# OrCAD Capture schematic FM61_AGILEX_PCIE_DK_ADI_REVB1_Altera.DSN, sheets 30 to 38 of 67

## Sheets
30 Micro SD: size B
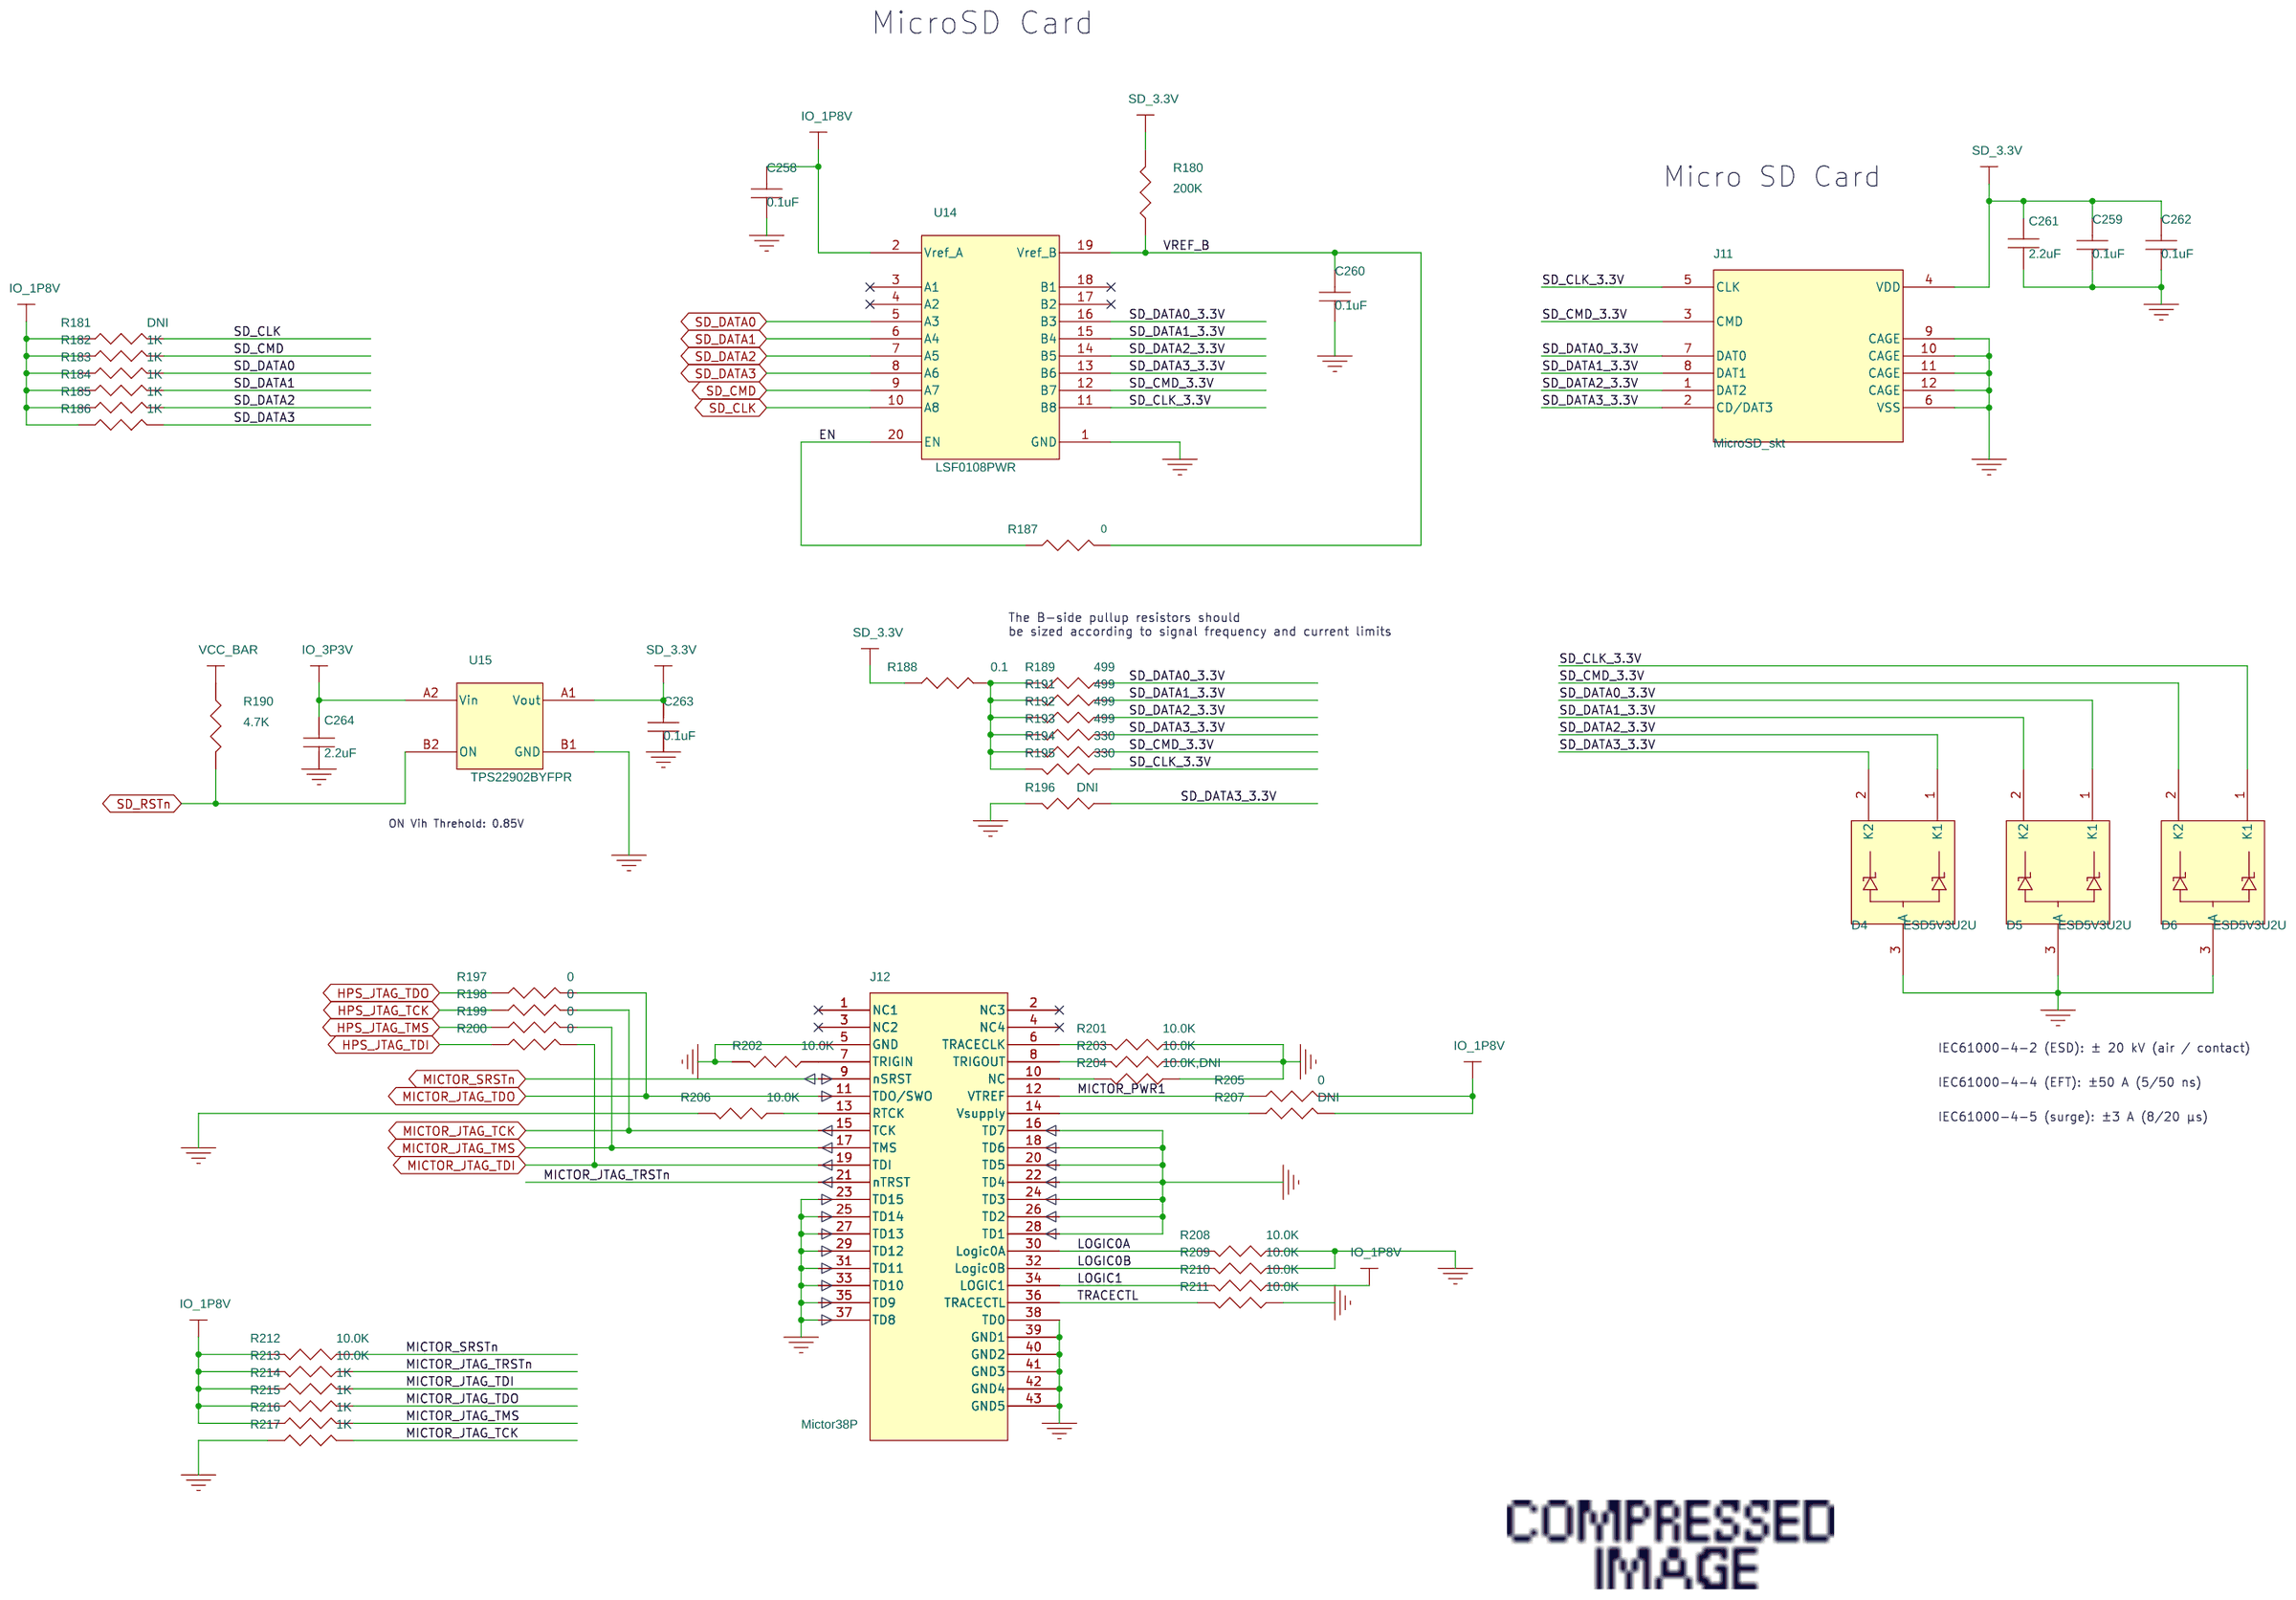
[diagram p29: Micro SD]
31 eMMC: size B
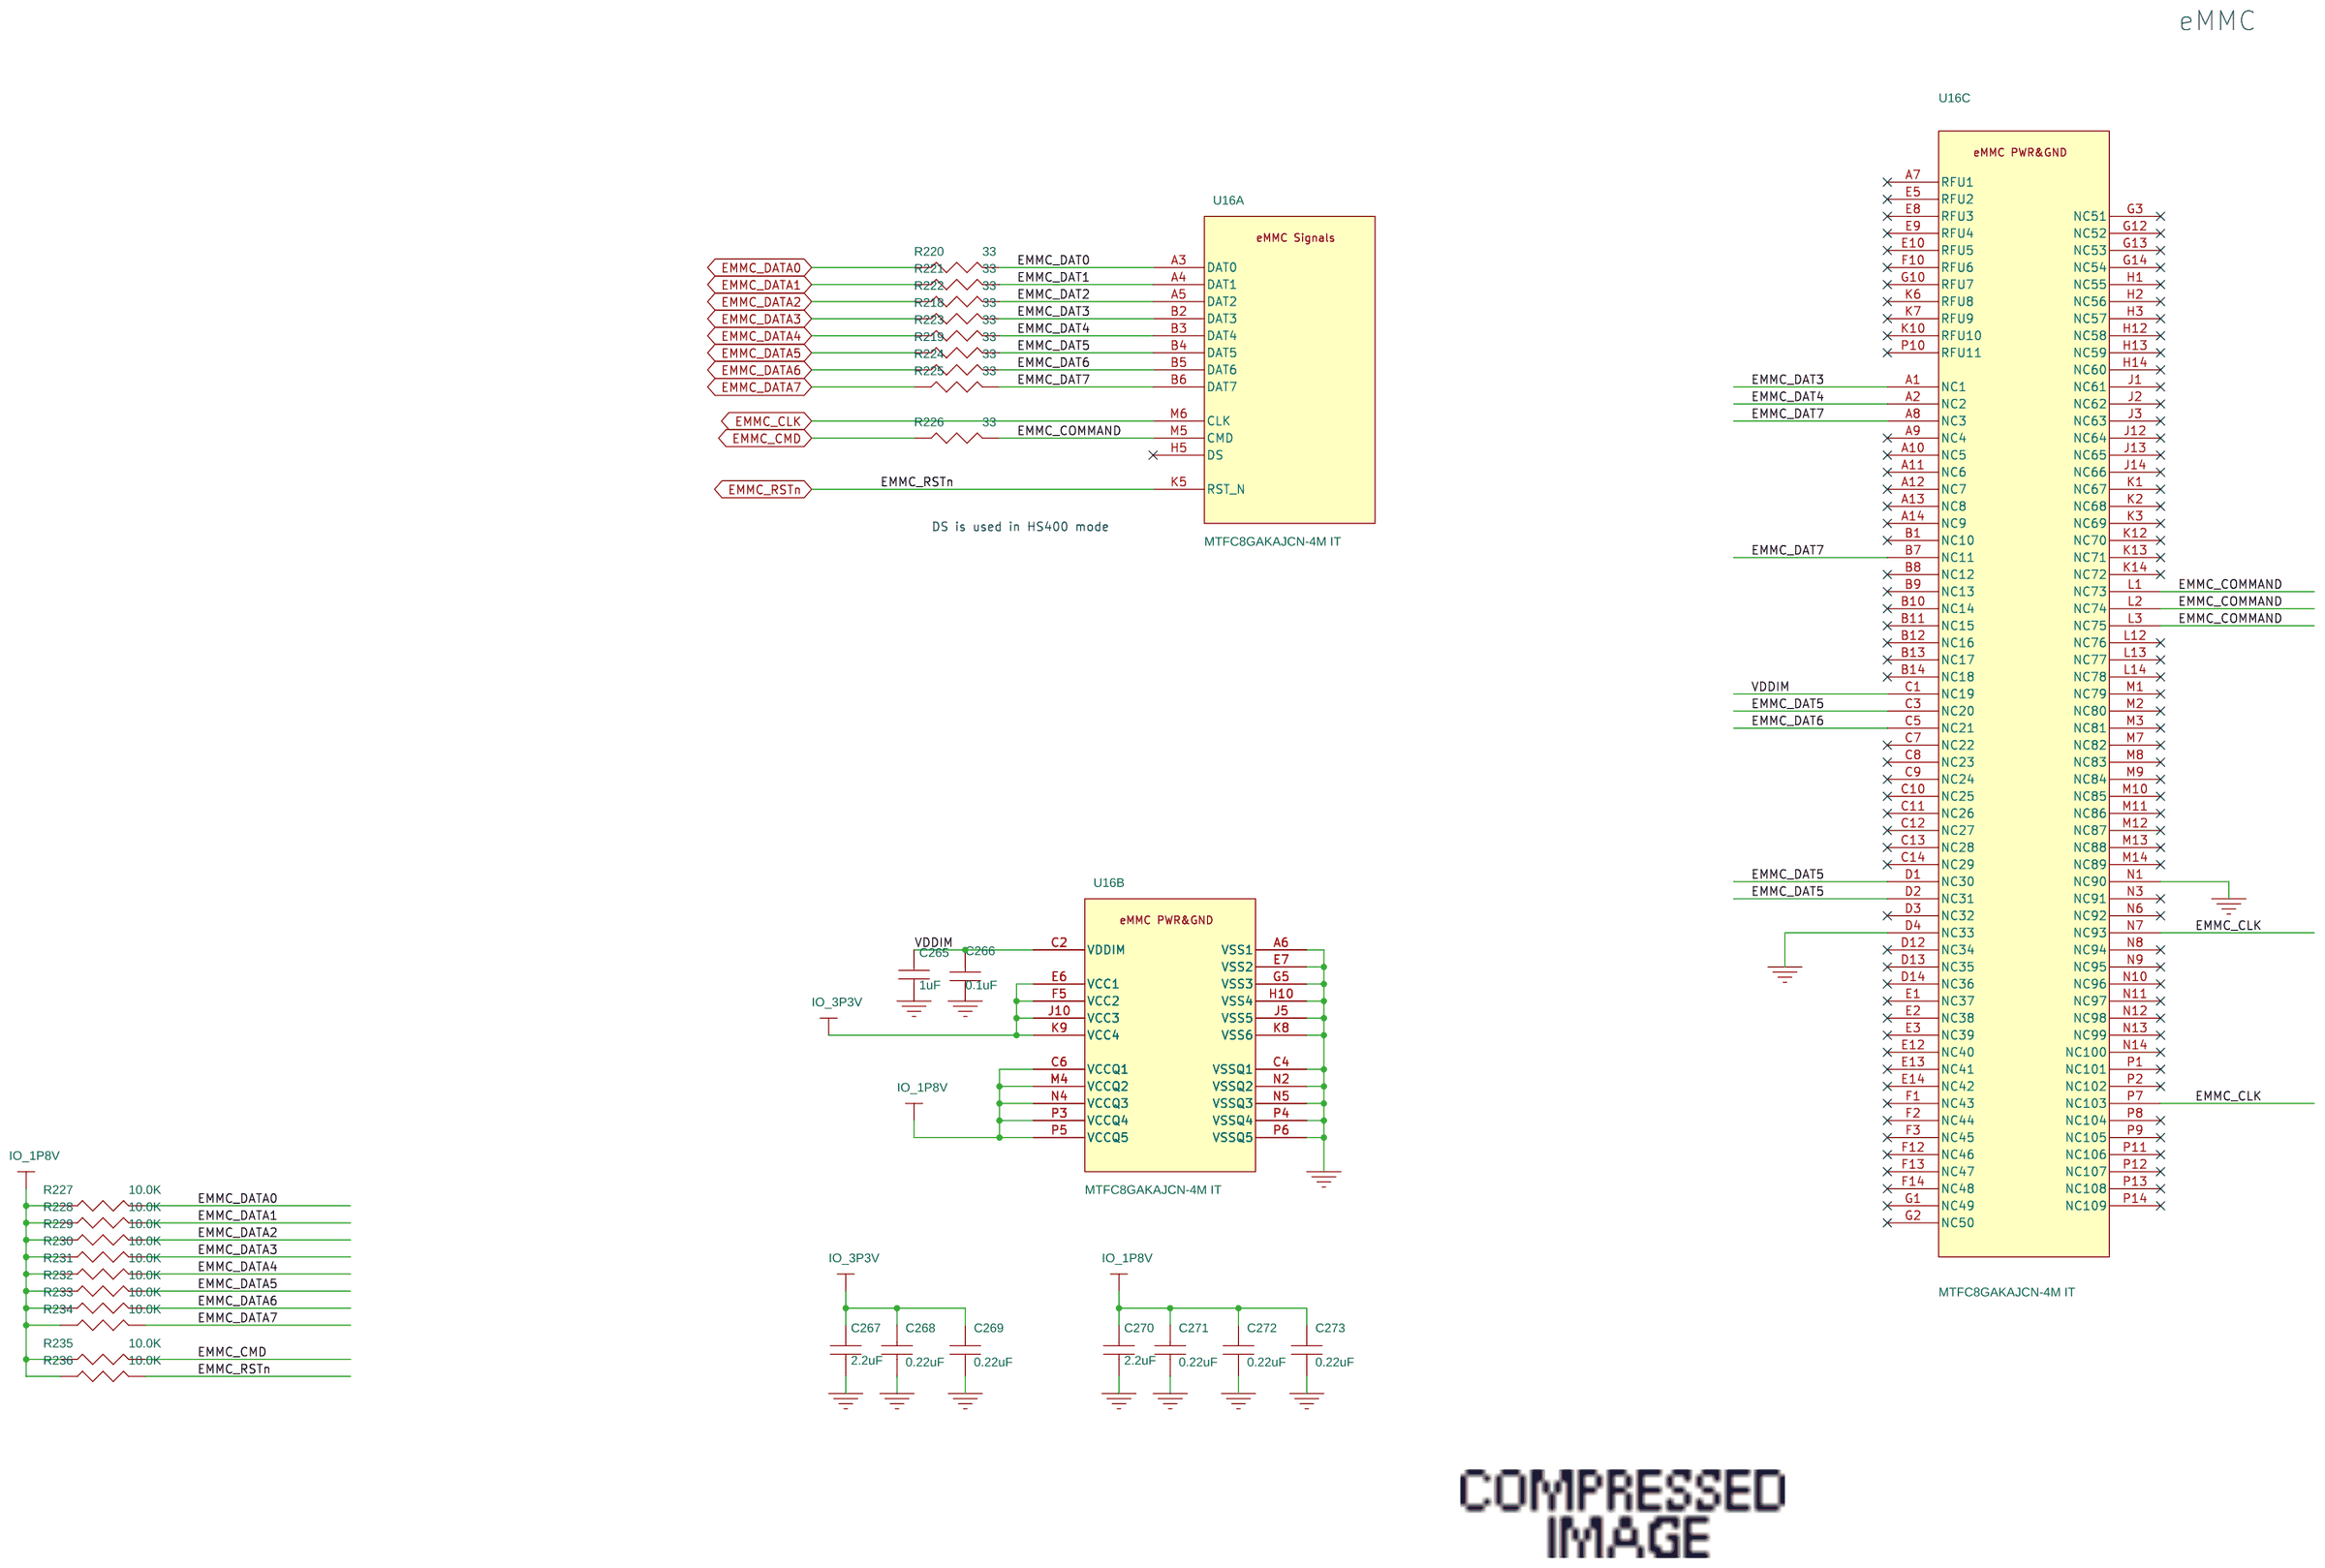
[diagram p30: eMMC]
32 FPGA BANK NC DNU: size B
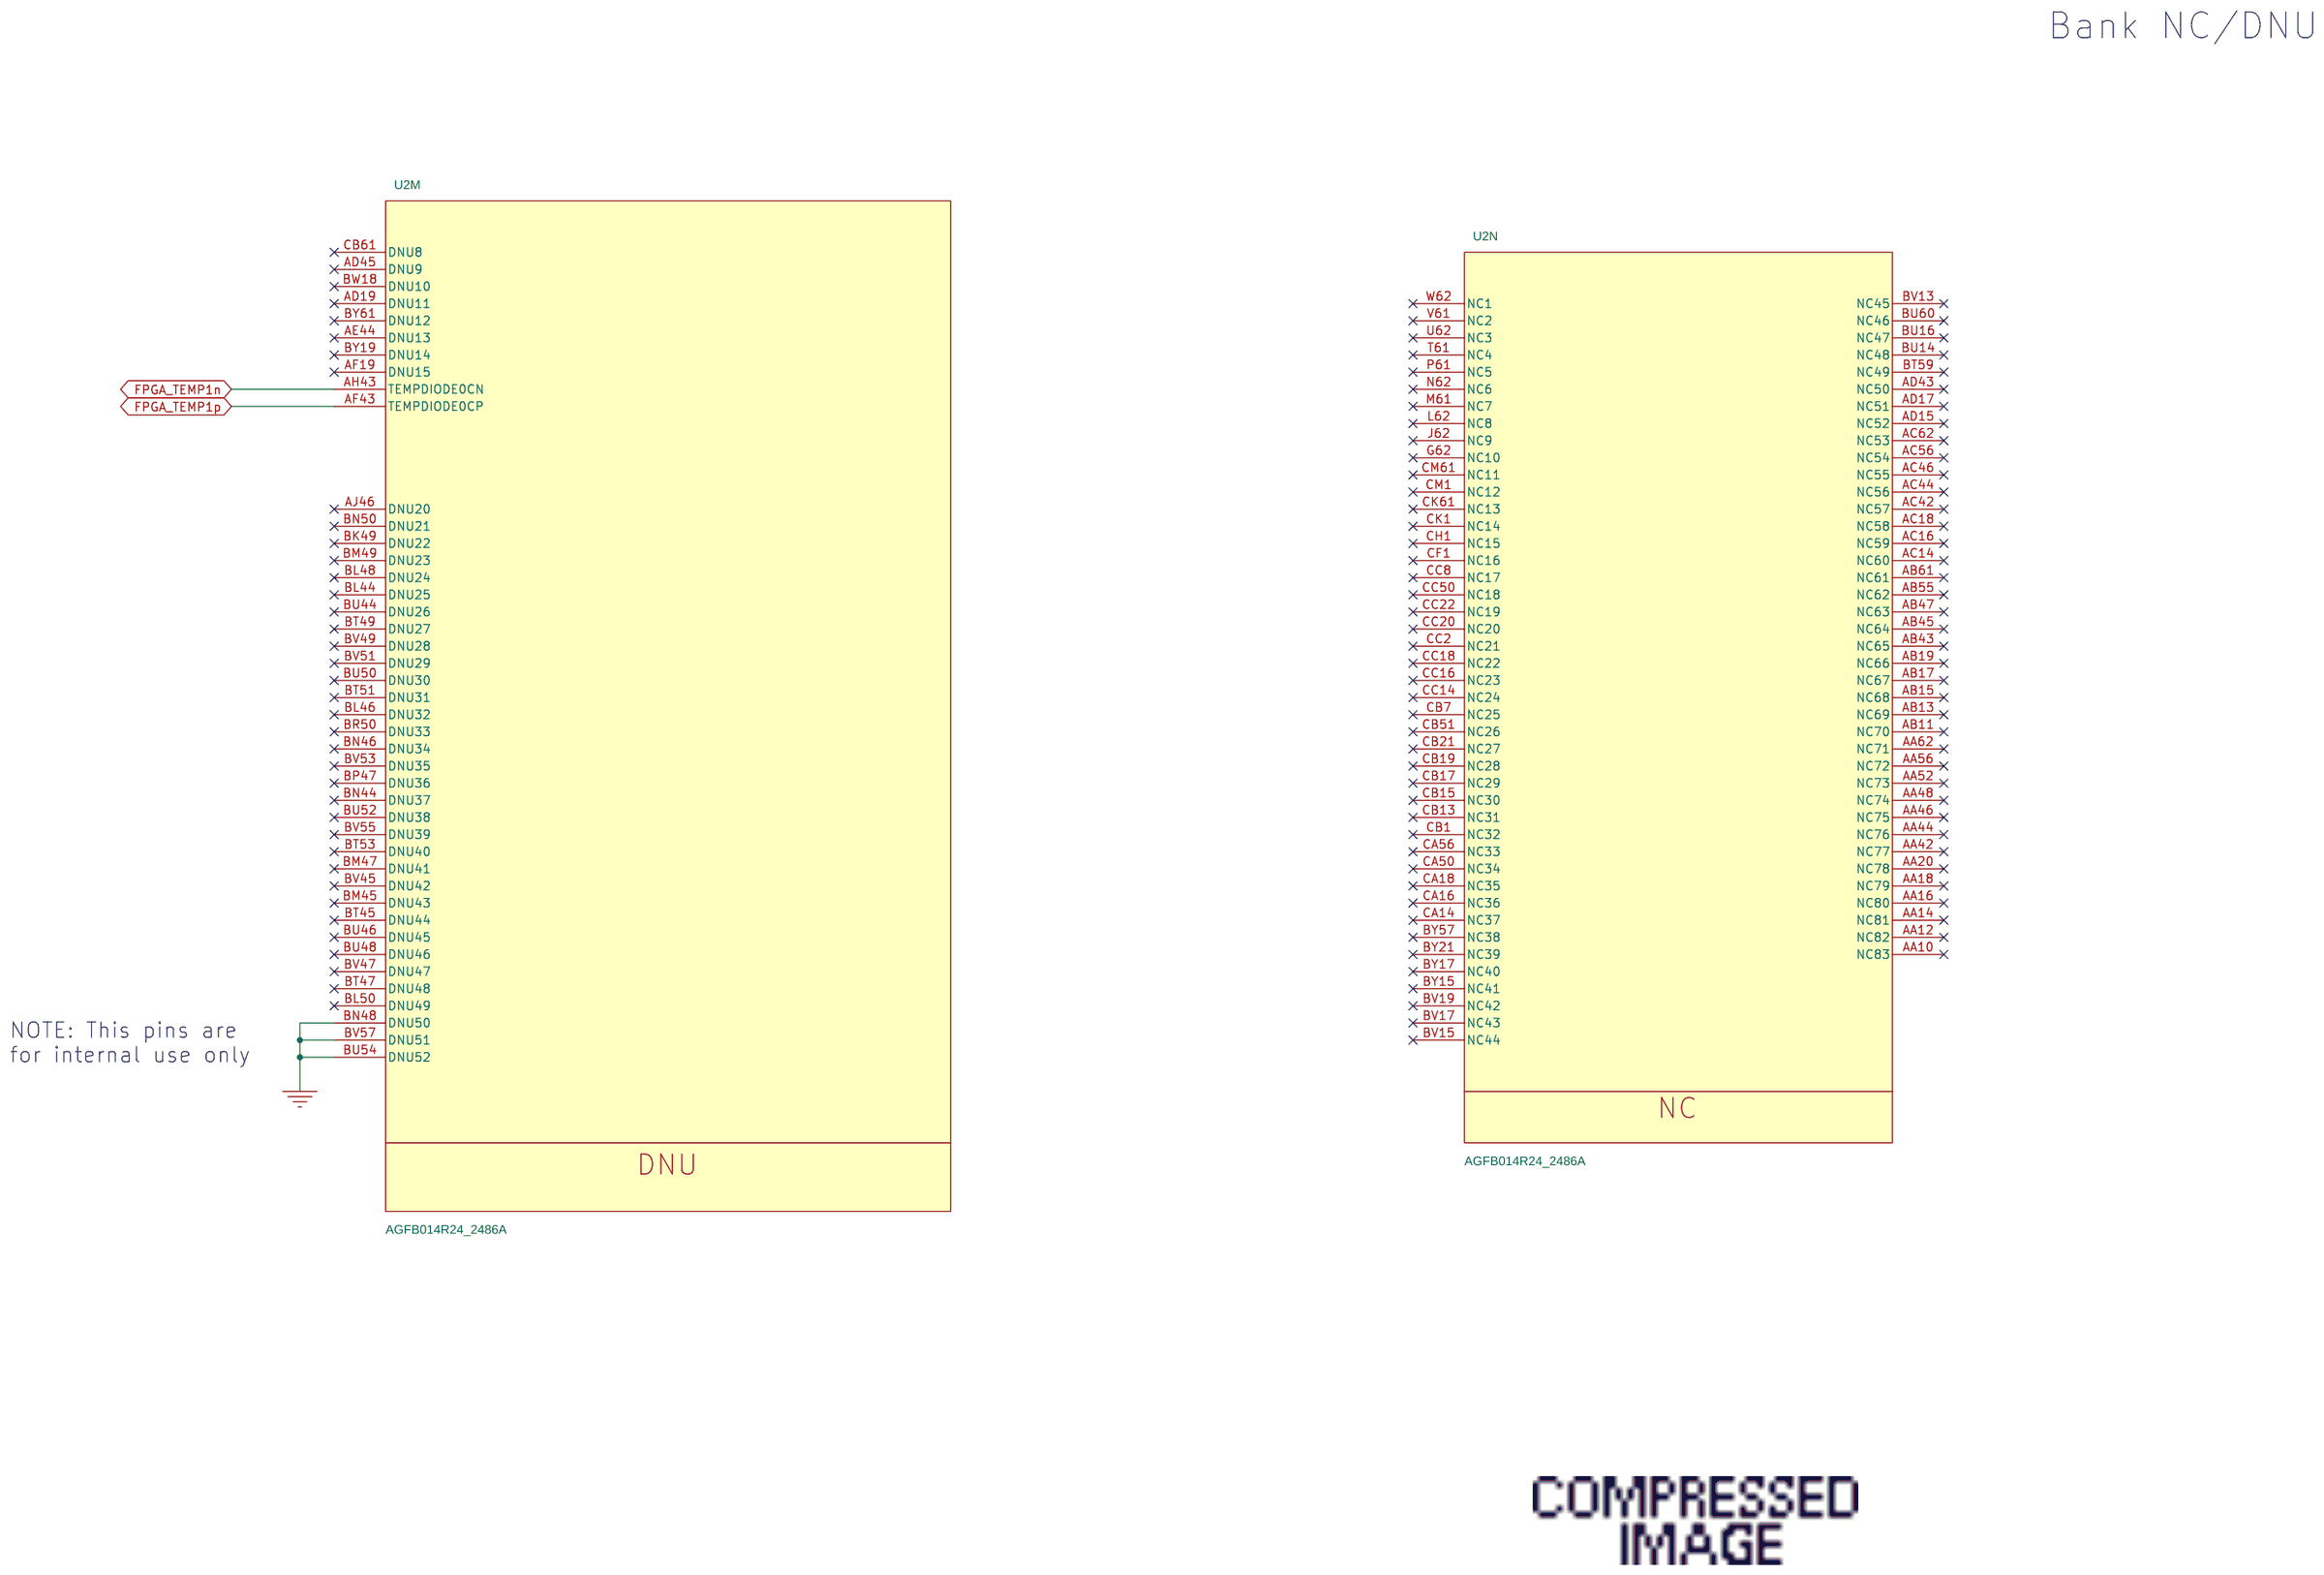
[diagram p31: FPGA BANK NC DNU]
33 FPGA Power 1: size B
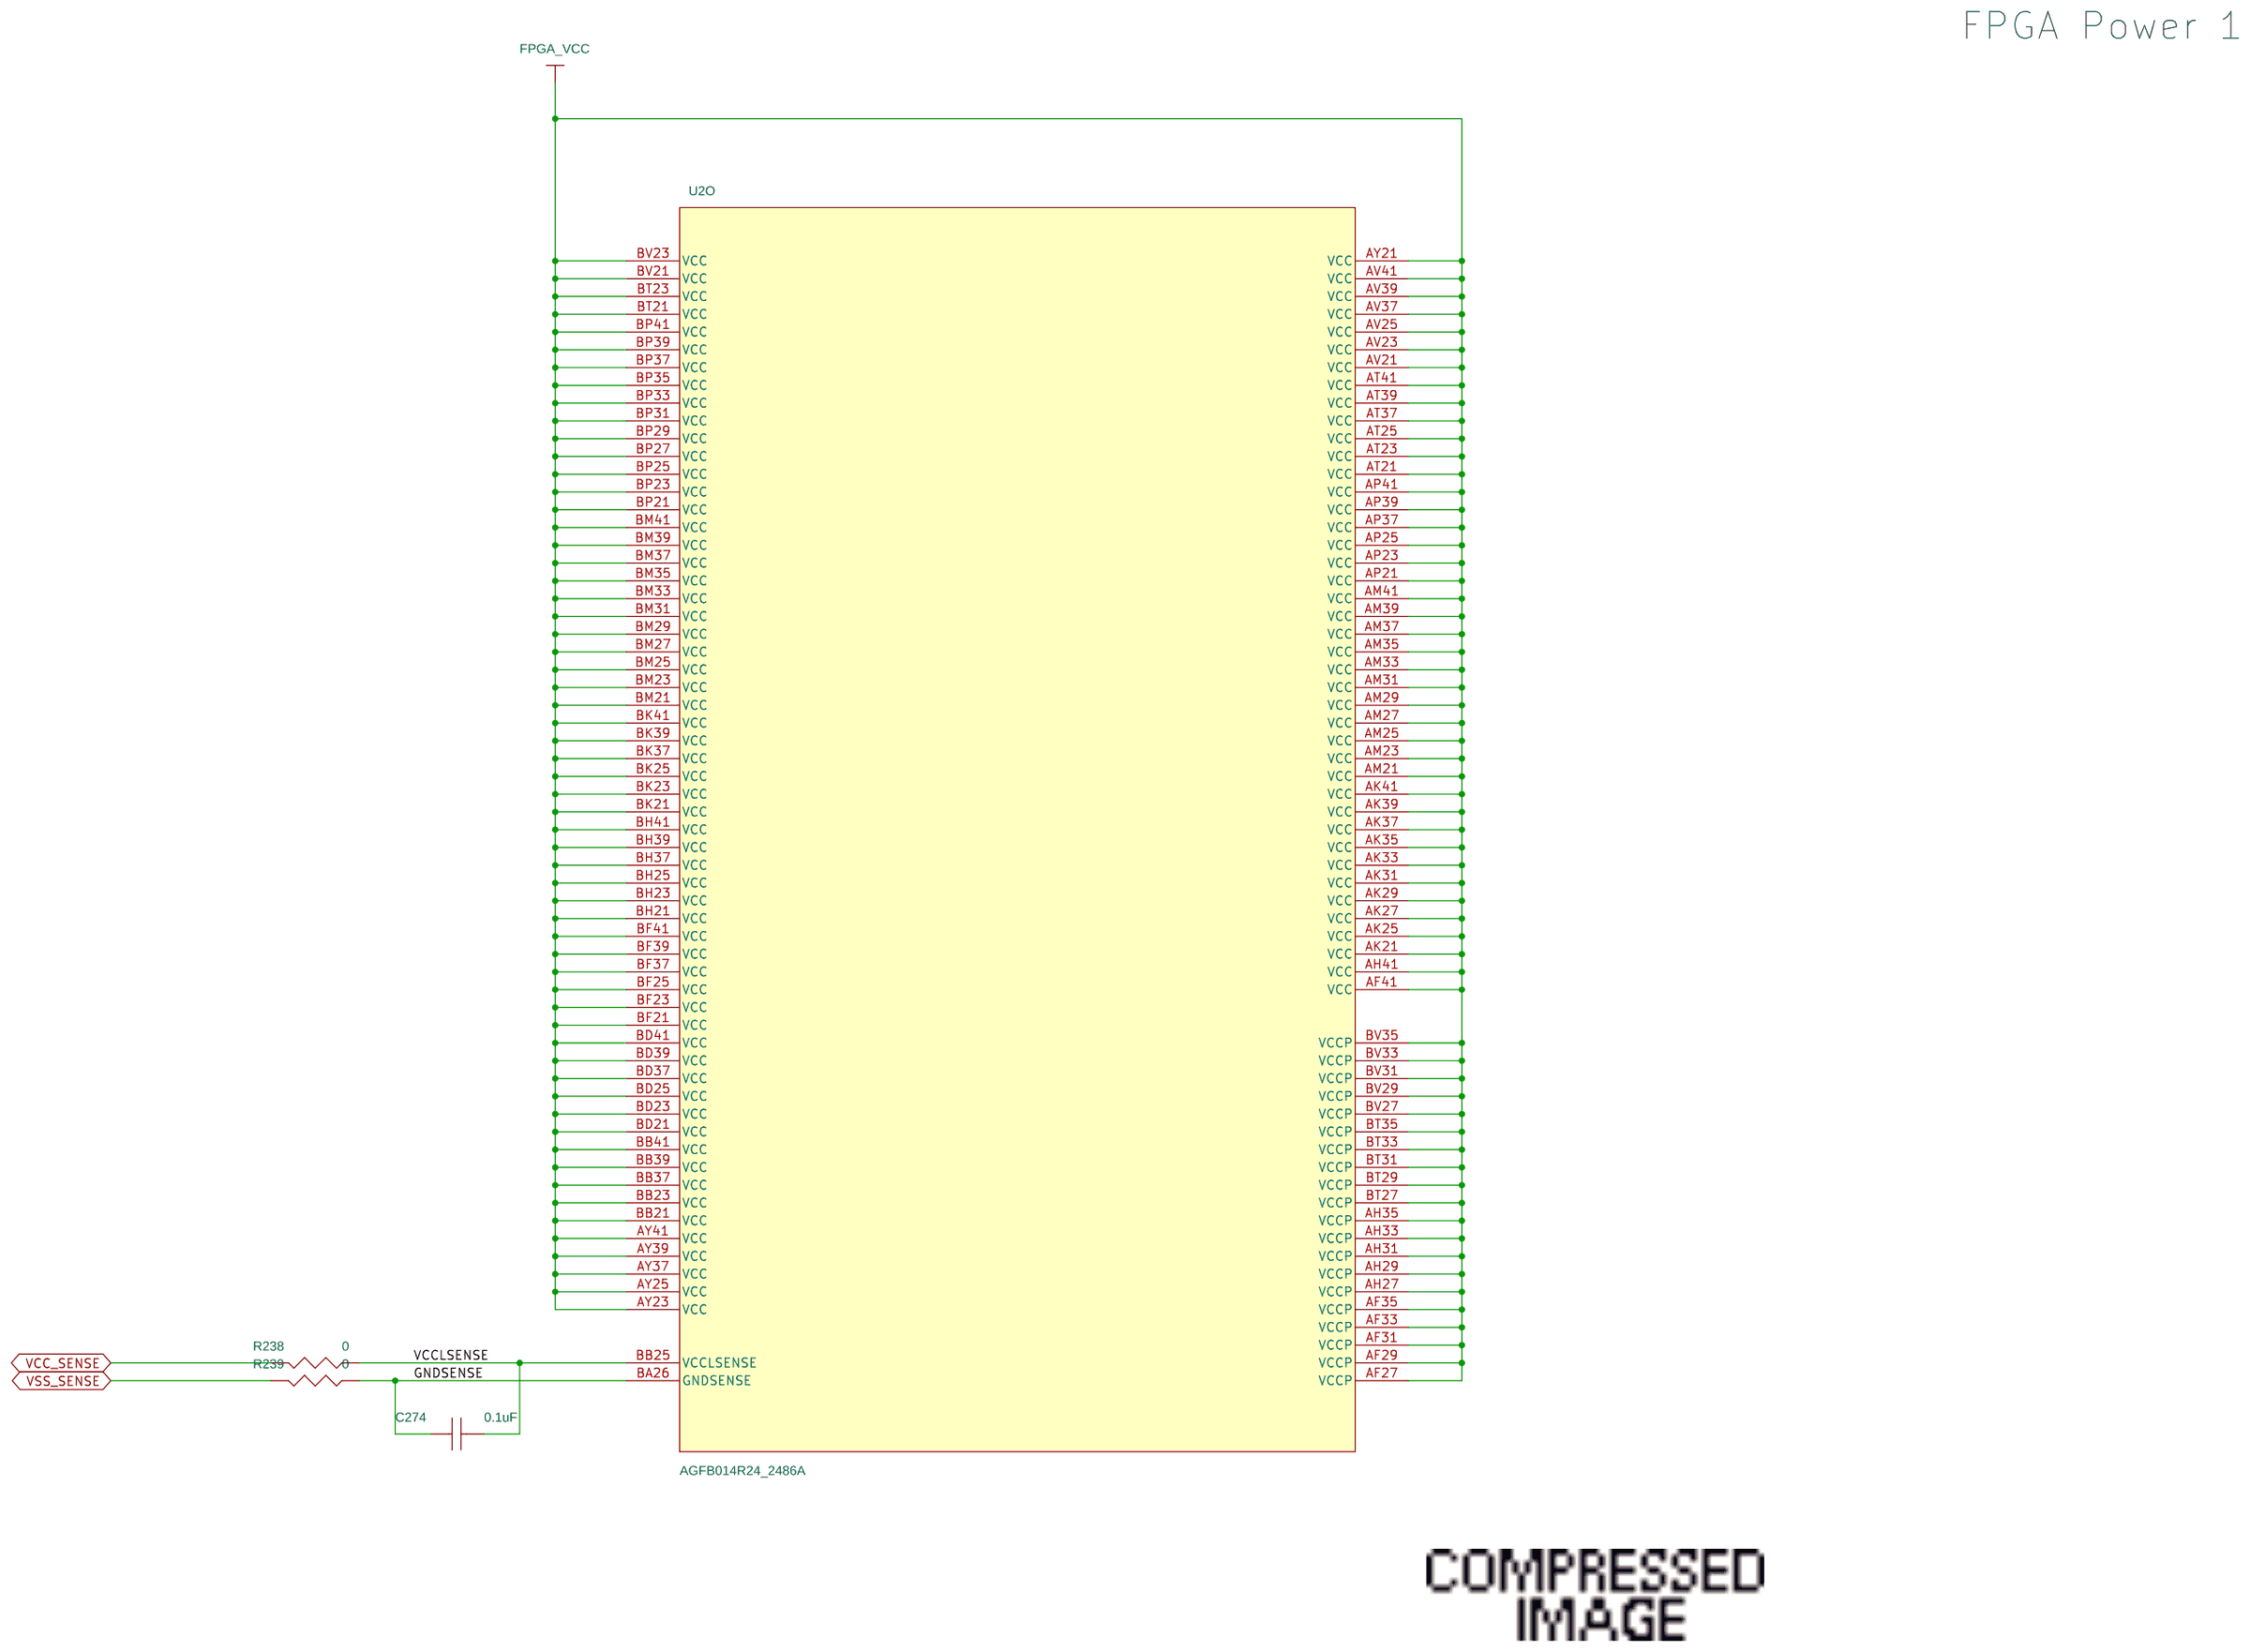
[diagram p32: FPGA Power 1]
34 FPGA Power 2: size B
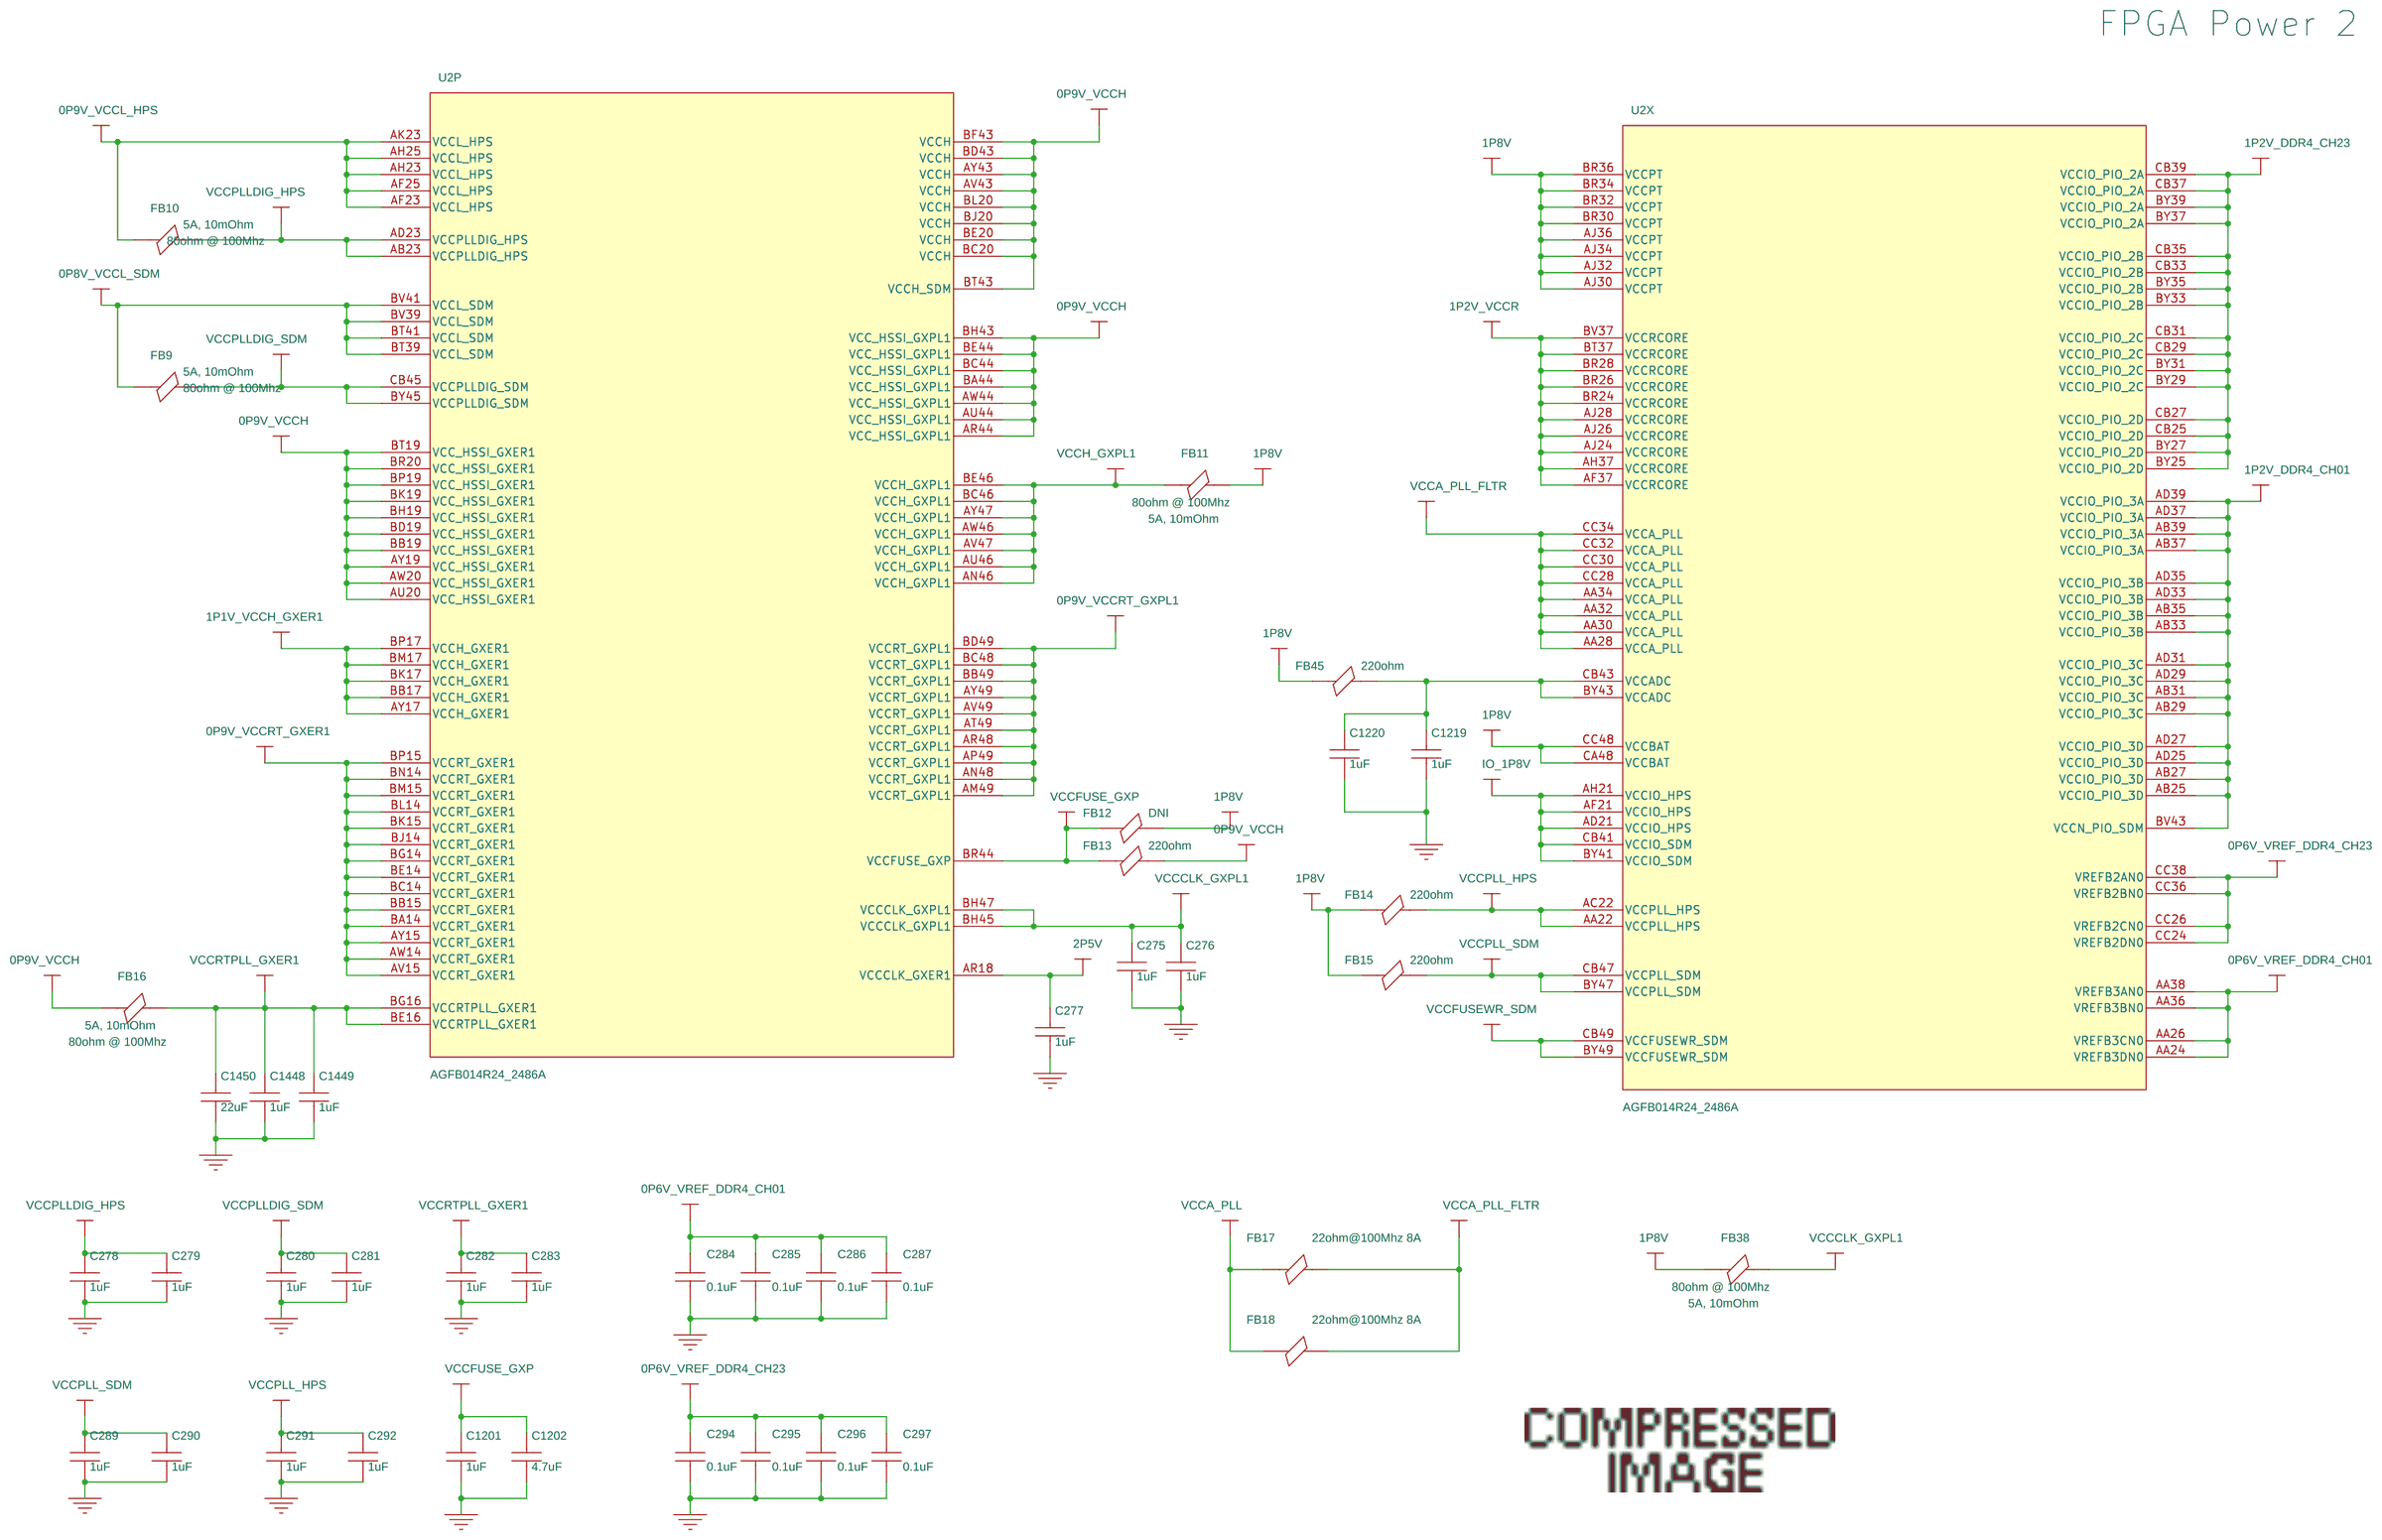
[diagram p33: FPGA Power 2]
35 FPGA Gnd 1: size B
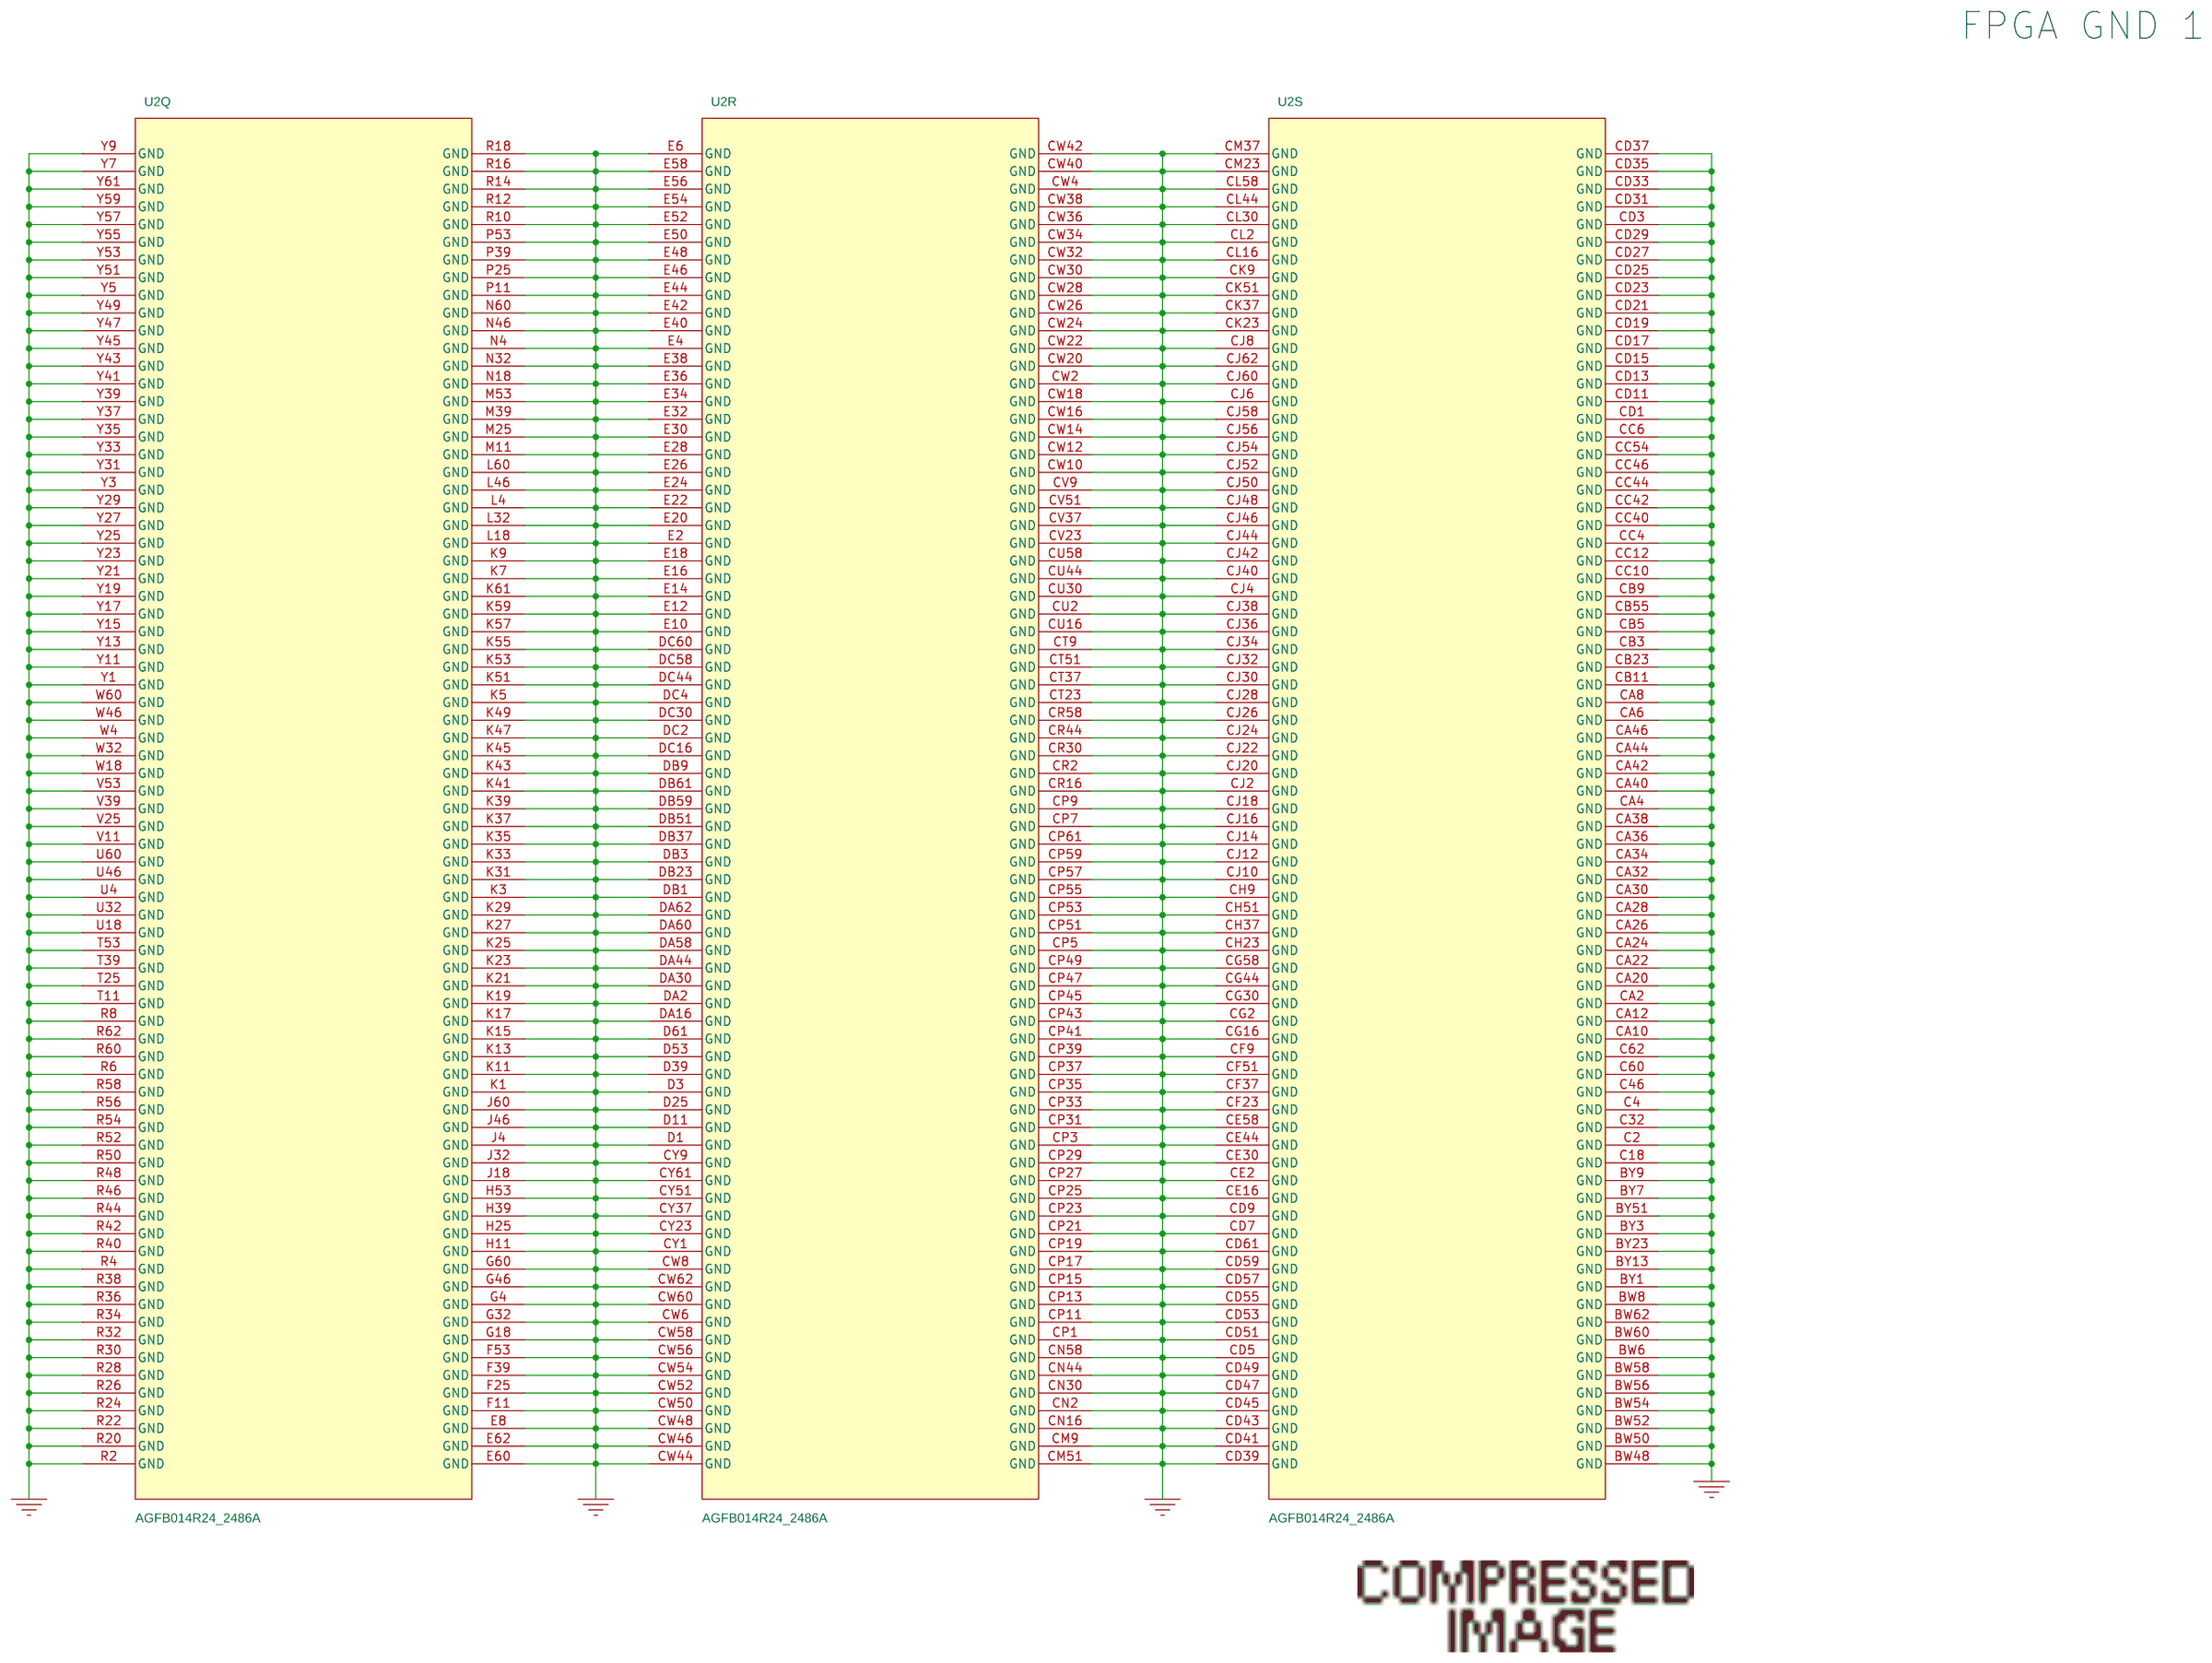
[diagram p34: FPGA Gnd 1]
36 FPGA Gnd 2: size B
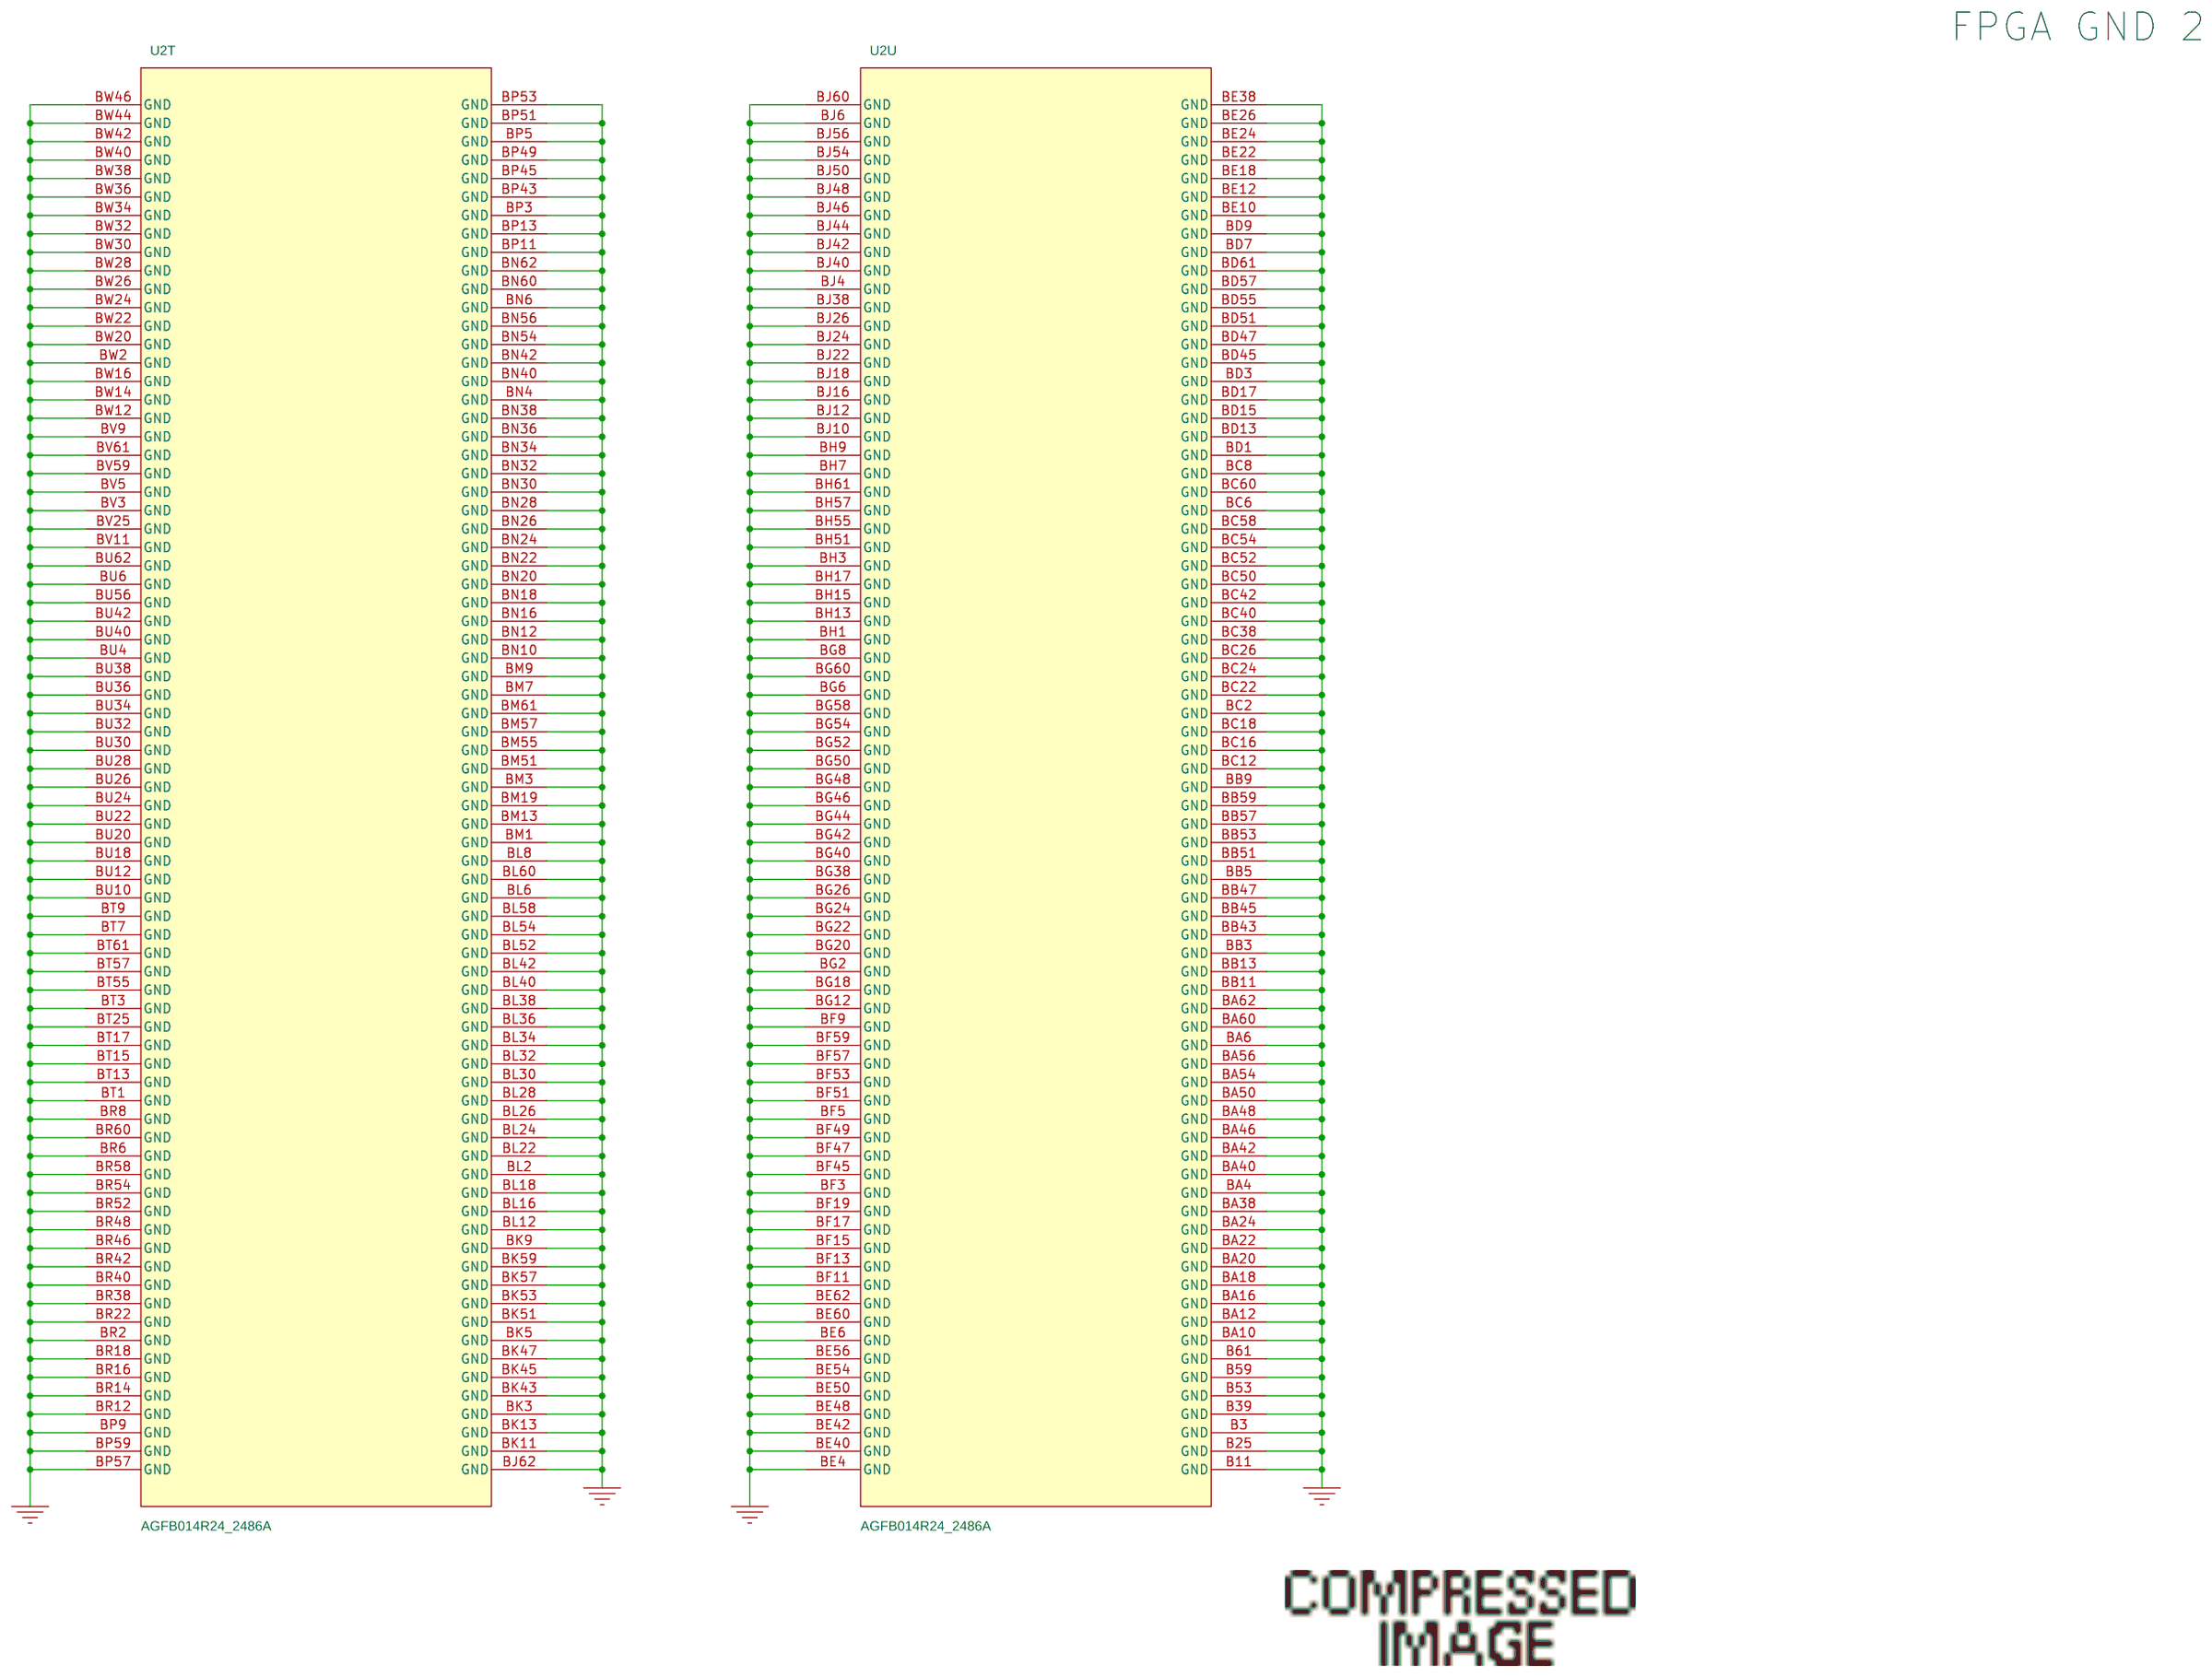
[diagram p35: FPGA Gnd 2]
37 FPGA Gnd 3: size B
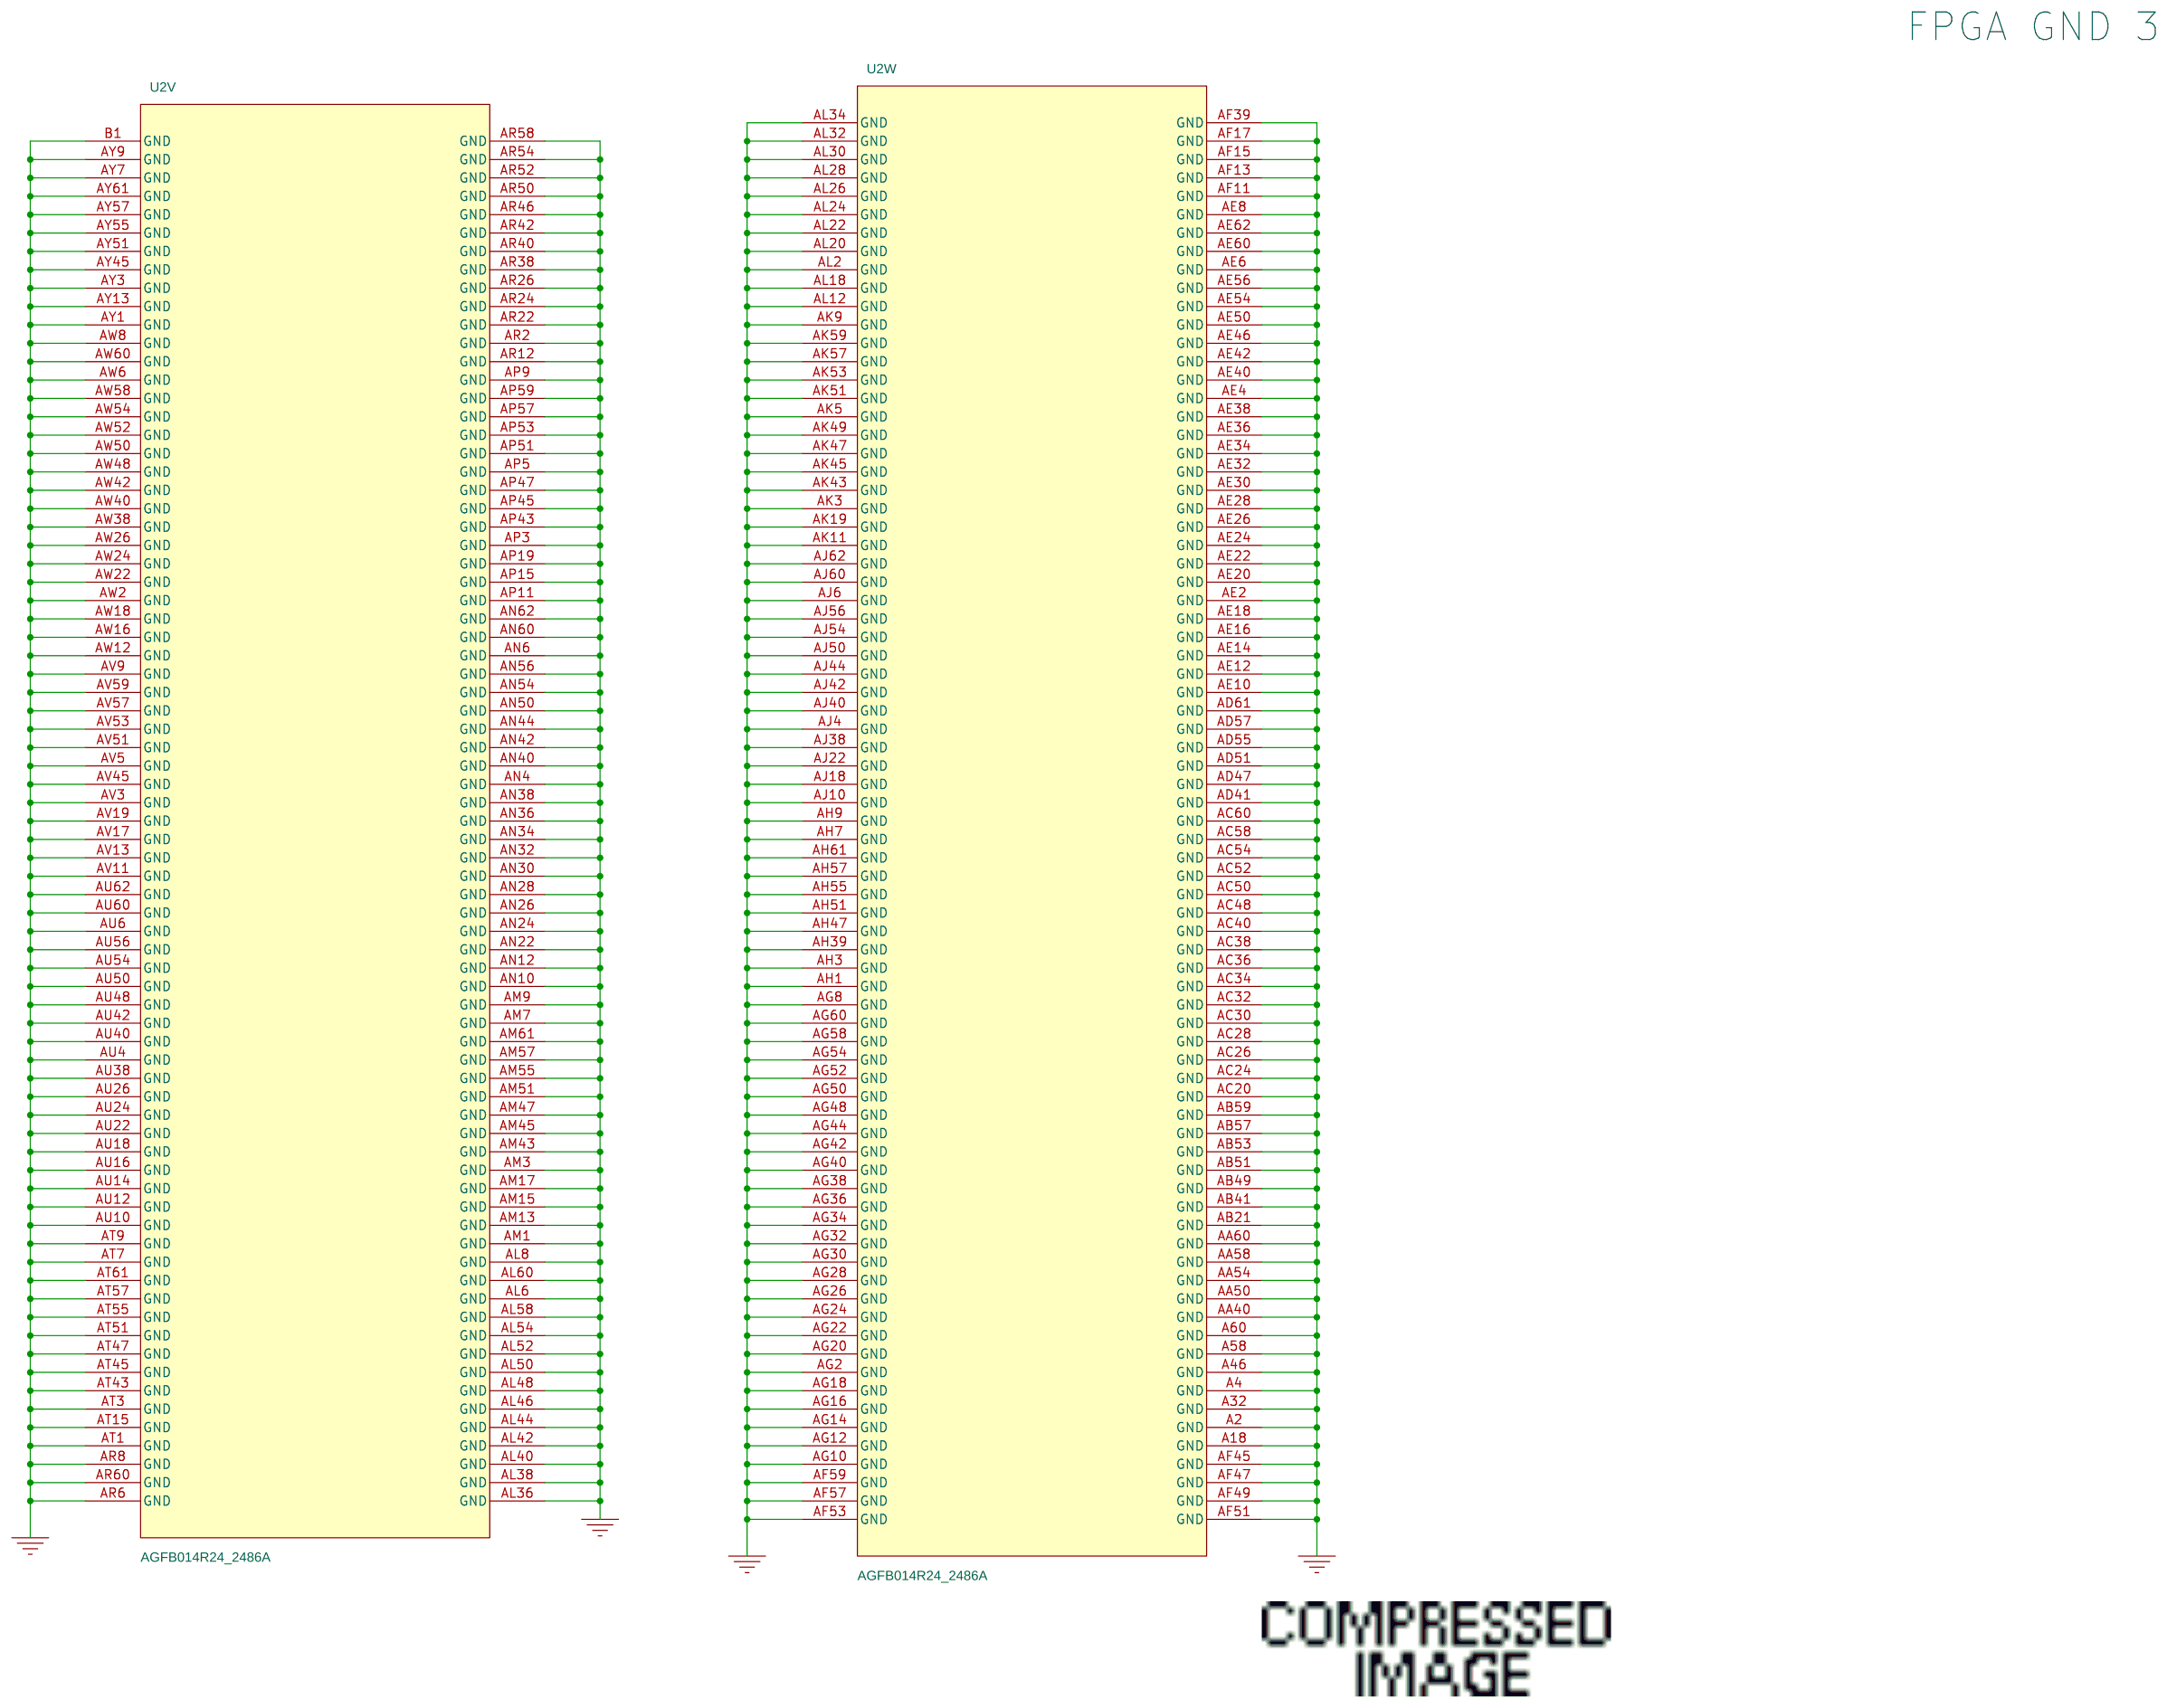
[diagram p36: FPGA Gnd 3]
38 Clock 1: size B
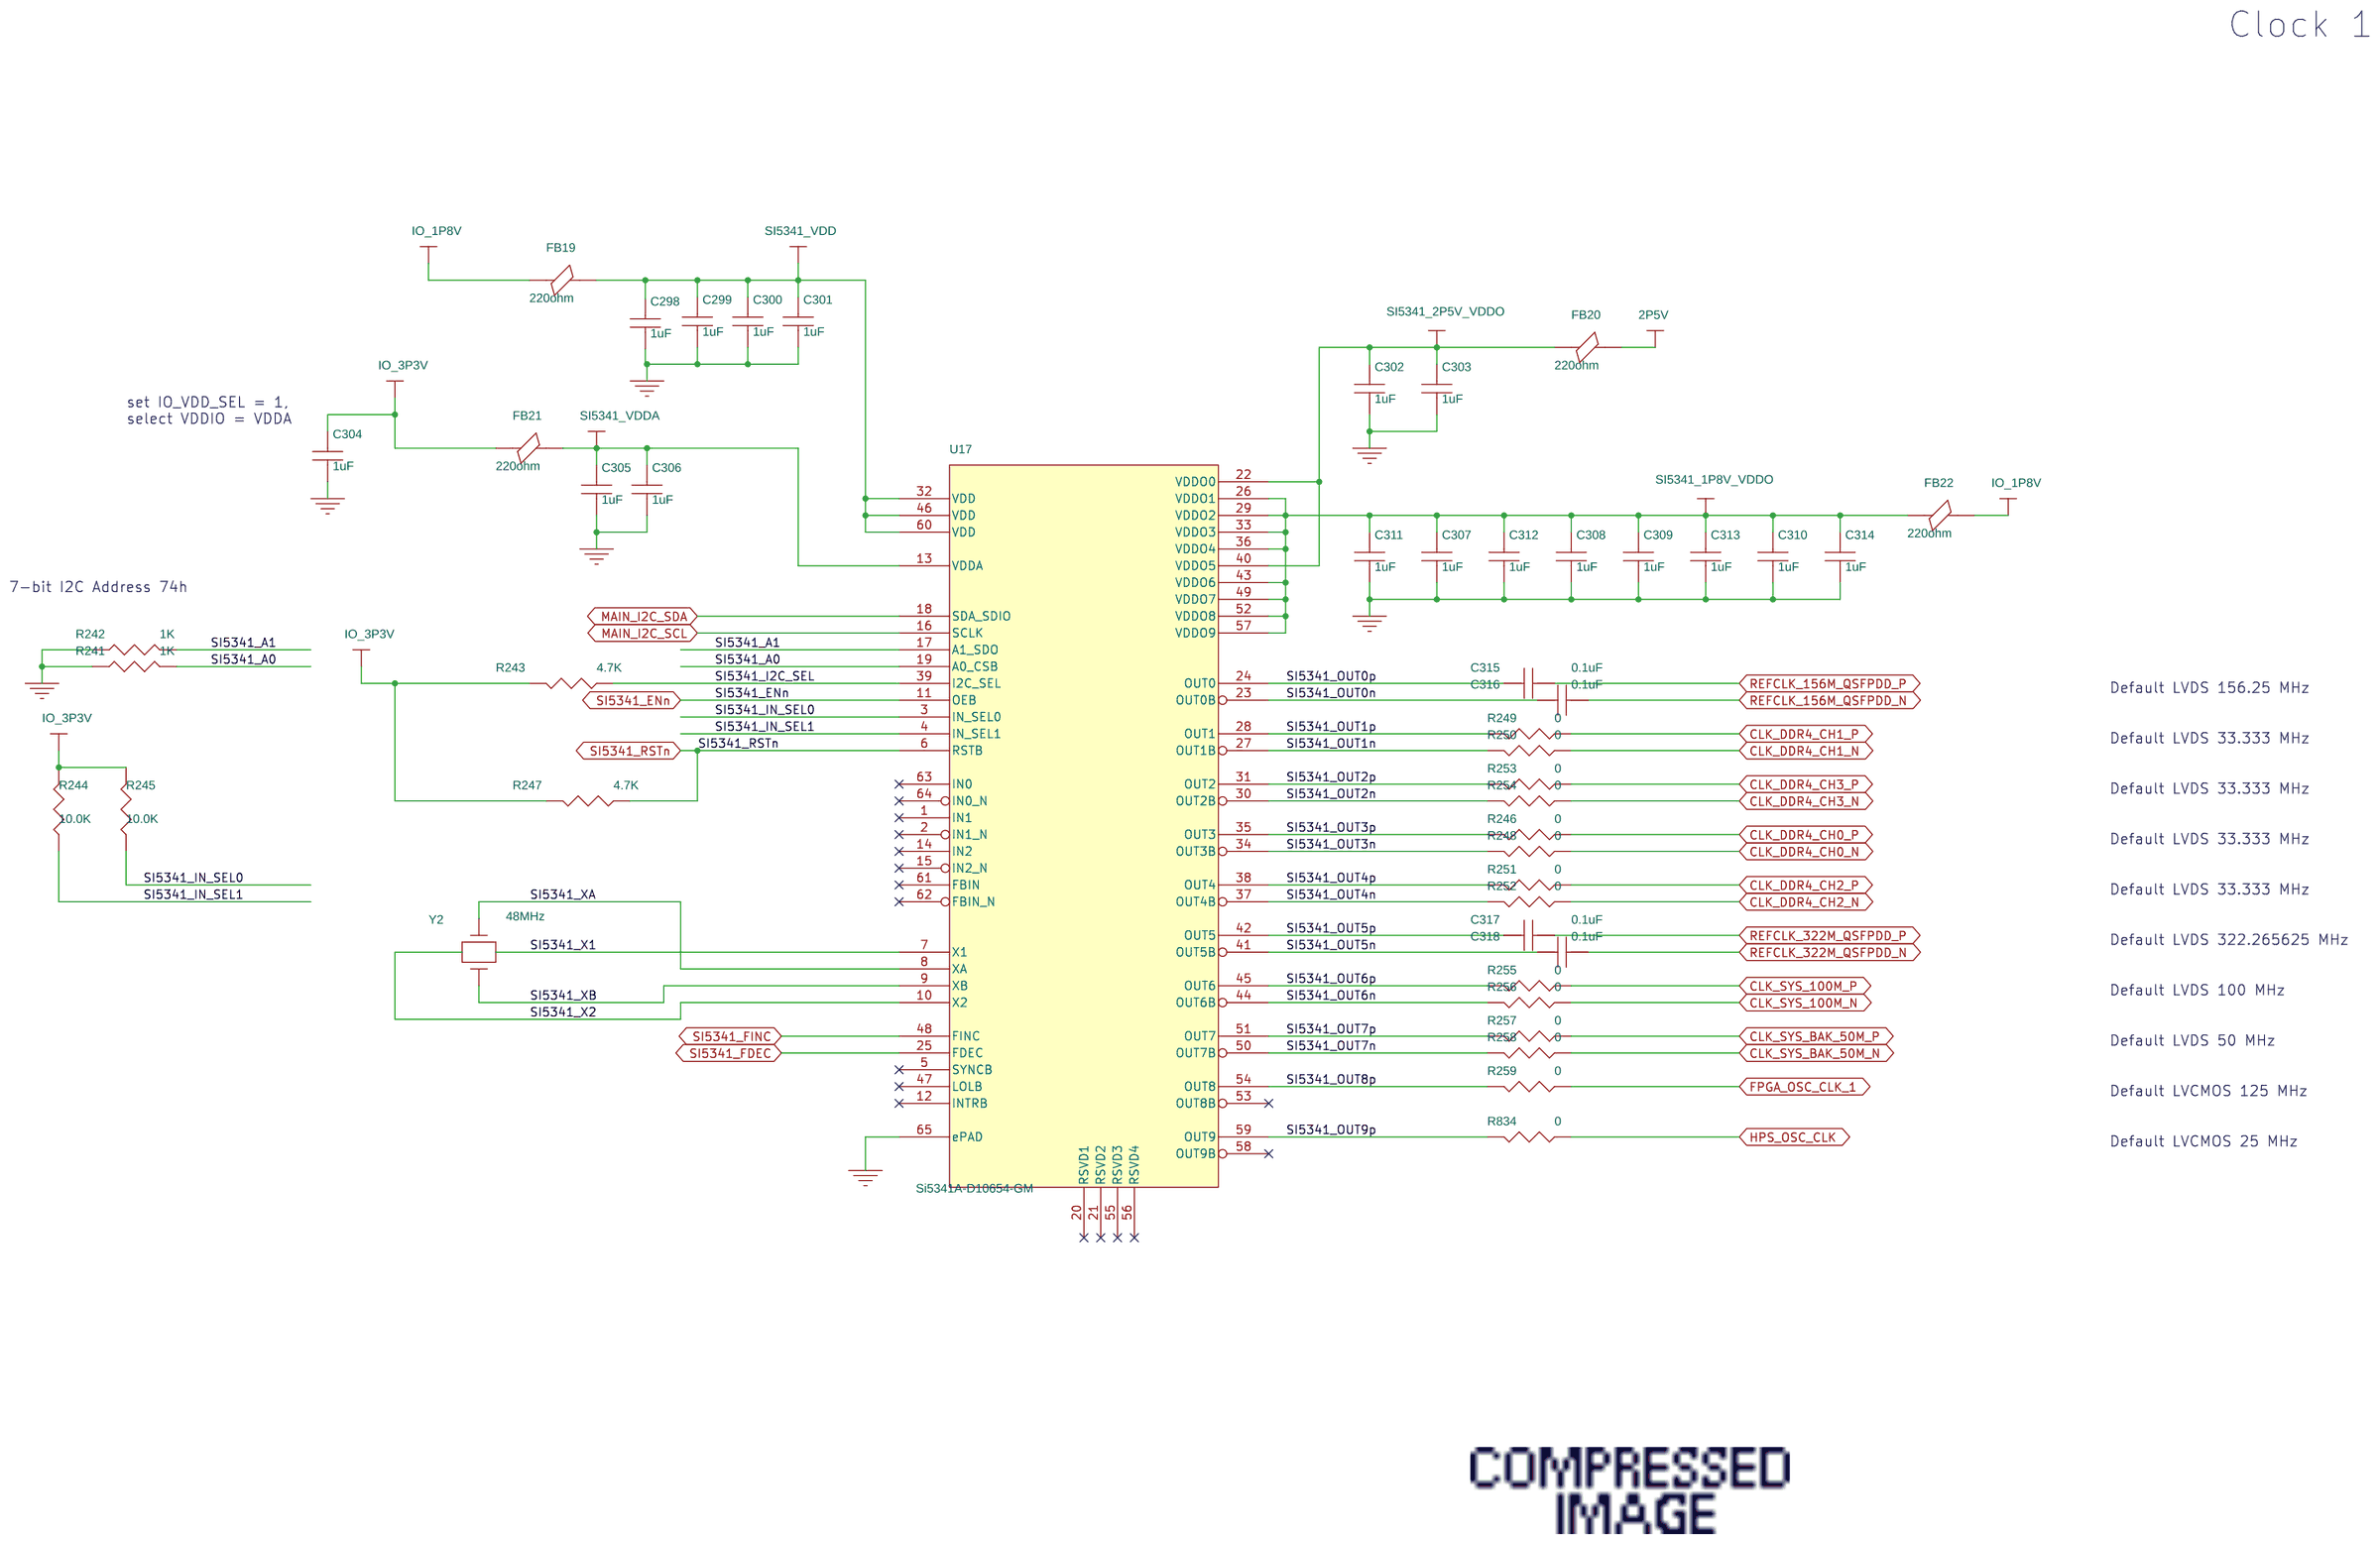
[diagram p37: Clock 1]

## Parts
sheet Clock 1
C298  1uF  [0402]
C299  1uF  [0402]
C300  1uF  [0402]
C301  1uF  [0402]
C302  1uF  [0402]
C303  1uF  [0402]
C304  1uF  [0402]
C305  1uF  [0402]
C306  1uF  [0402]
C307  1uF  [0402]
C308  1uF  [0402]
C309  1uF  [0402]
C310  1uF  [0402]
C311  1uF  [0402]
C312  1uF  [0402]
C313  1uF  [0402]
C314  1uF  [0402]
C315  0.1uF  [0402]
C316  0.1uF  [0402]
C317  0.1uF  [0402]
C318  0.1uF  [0402]
FB19  220ohm  [0402]
FB20  220ohm  [0402]
FB21  220ohm  [0402]
FB22  220ohm  [0402]
R241  1K  [0402]
R242  1K  [0402]
R243  4.7K  [0402]
R244  10.0K  [0402]
R245  10.0K  [0402]
R246  0  [0402]
R247  4.7K  [0402]
R248  0  [0402]
R249  0  [0402]
R250  0  [0402]
R251  0  [0402]
R252  0  [0402]
R253  0  [0402]
R254  0  [0402]
R255  0  [0402]
R256  0  [0402]
R257  0  [0402]
R258  0  [0402]
R259  0  [0402]
R834  0  [0402]
U17  Si5341A-D10654-GM  [QFN64_9x9_SI5341]
Y2  48MHz  [XTAL_3mmx2mm]
sheet eMMC
C265  1uF  [0603]
C266  0.1uF  [0402]
C267  2.2uF  [0603]
C268  0.22uF  [0402]
C269  0.22uF  [0402]
C270  2.2uF  [0603]
C271  0.22uF  [0402]
C272  0.22uF  [0402]
C273  0.22uF  [0402]
R218  33  [0402]
R219  33  [0402]
R220  33  [0402]
R221  33  [0402]
R222  33  [0402]
R223  33  [0402]
R224  33  [0402]
R225  33  [0402]
R226  33  [0402]
R227  10.0K  [0402]
R228  10.0K  [0402]
R229  10.0K  [0402]
R230  10.0K  [0402]
R231  10.0K  [0402]
R232  10.0K  [0402]
R233  10.0K  [0402]
R234  10.0K  [0402]
R235  10.0K  [0402]
R236  10.0K  [0402]
U16  MTFC8GAKAJCN-4M IT  [VFBGA-153]  (sections A,B,C)
sheet FPGA Gnd 2
U2  AGFB014R24_2486A  [FBGA2486A_HEX]  (sections A,B,C,D,E,F,G,H,I,J,K,L,M,N,O,P,Q,R,S,T,U,V,W,X)
sheet FPGA Power 1
C274  0.1uF  [0402]
R238  0  [0402]
R239  0  [0402]
sheet FPGA Power 2
C275  1uF  [0201]
C276  1uF  [0201]
C277  1uF  [0201]
C278  1uF  [0201]
C279  1uF  [0201]
C280  1uF  [0201]
C281  1uF  [0201]
C282  1uF  [0201]
C283  1uF  [0201]
C284  0.1uF  [0402]
C285  0.1uF  [0402]
C286  0.1uF  [0402]
C287  0.1uF  [0402]
C289  1uF  [0201]
C290  1uF  [0201]
C291  1uF  [0201]
C292  1uF  [0201]
C294  0.1uF  [0402]
C295  0.1uF  [0402]
C296  0.1uF  [0402]
C297  0.1uF  [0402]
C1201  1uF  [0201]
C1202  4.7uF  [0603]
C1219  1uF  [0201]
C1220  1uF  [0201]
C1448  1uF  [0201]
C1449  1uF  [0201]
C1450  22uF  [0805]
FB9  80ohm @ 100Mhz  [0805]
FB10  80ohm @ 100Mhz  [0805]
FB11  80ohm @ 100Mhz  [0805]
FB12  DNI  [0402]
FB13  220ohm  [0402]
FB14  220ohm  [0402]
FB15  220ohm  [0402]
FB16  80ohm @ 100Mhz  [0805]
FB17  22ohm@100Mhz 8A  [0603]
FB18  22ohm@100Mhz 8A  [0603]
FB38  80ohm @ 100Mhz  [0805]
FB45  220ohm  [0402]
sheet Micro SD
C258  0.1uF  [0402]
C259  0.1uF  [0402]
C260  0.1uF  [0402]
C261  2.2uF  [0603]
C262  0.1uF  [0402]
C263  0.1uF  [0402]
C264  2.2uF  [0603]
D4  ESD5V3U2U  [TSLP-3-7]
D5  ESD5V3U2U  [TSLP-3-7]
D6  ESD5V3U2U  [TSLP-3-7]
J11  MicroSD_skt  [WURTH_MICRO-SD_CARD]
J12  Mictor38P  [SMT38]
R180  200K  [0402]
R181  DNI  [0402]
R182  1K  [0402]
R183  1K  [0402]
R184  1K  [0402]
R185  1K  [0402]
R186  1K  [0402]
R187  0  [0402]
R188  0.1  [0805]
R189  499  [0603]
R190  4.7K  [0402]
R191  499  [0603]
R192  499  [0603]
R193  499  [0603]
R194  330  [0603]
R195  330  [0603]
R196  DNI  [0402]
R197  0  [0402]
R198  0  [0402]
R199  0  [0402]
R200  0  [0402]
R201  10.0K  [0402]
R202  10.0K  [0402]
R203  10.0K  [0402]
R204  10.0K,DNI  [0402]
R205  0  [0603]
R206  10.0K  [0402]
R207  DNI  [0603]
R208  10.0K  [0402]
R209  10.0K  [0402]
R210  10.0K  [0402]
R211  10.0K  [0402]
R212  10.0K  [0402]
R213  10.0K  [0402]
R214  1K  [0402]
R215  1K  [0402]
R216  1K  [0402]
R217  1K  [0402]
U14  LSF0108PWR  [tssop20]
U15  TPS22902BYFPR  [TPS22902BYFPR]

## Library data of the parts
C298-C314 = CAP: CAP, X5R, 1UF, 20%, 10V, 0402,; IPN: H67656-001; Item Num: P03-15479R; Lead Free Status: Yes; Manufacturer: Murata; Manufacturer Part Num: GRM155R61A105KE15D; Num Pins: 2; Part Class: CAPACITORS; RoHS Compliant: Yes; Voltage: 10V
C315-C318 = CAP: CAP CER 0.1UF 25V 20% X7R 0402; Dielectric: X5R; IPN: K13660-001; Item Num: P03-17618R; LIFECYCLE_PHASE: Active; Lead Free Status: Lead Free; Manufacturer: TDK Electronics; Manufacturer Part Num: C1005X7R1E104M; Num Pins: 2; Part Class: CAPACITORS; Price: 0.07; RoHS Compliant: RoHS Compliant; Tolerance: +80%/-20%
FB12-FB15 FB19-FB22 FB45 = BEAD_FERRITE_SM: IND - SMD EMI FILTERS/CHIP FERRITE BEAD, 220-OHM @ 100MHZ, 0.35-OHM DCR, 0402; IPN: G79186-002; Imax (A): 300mA; Item Num: P04-17068R; Manufacturer: Wurth Elektronik; Manufacturer Part Num: 742792780; Rdc (Ohms): 350mOhm; Tolerance (%): 25%
R241 R242 = RESISTOR: RES,1.00K OHMS,1.0%,1/16W,0402; IPN: G60609-021; Item Num: P02-11372R; Lead Free Status: No; Manufacturer: Panasonic; Manufacturer Part Num: ERJ-2RKF1001X; Num Pins: 2; Part Class: Resistors
R243 R247 = RESISTOR: RES 4.7K OHM 1/16W 5% 0402 SMD; IPN: H30885-001; Item Num: P02-14032R; Lead Free Status: No; Manufacturer: Panasonic; Manufacturer Part Num: ERJ-2GEJ472X; Manufacturer's Part No.: ERJ-2GEJ472X; Num Pins: 2; Part Class: RESISTORS; Price: 0; RoHS Compliant: Yes
R244 R245 = RESISTOR: RES,10.0K OHMS,1.0%,1/16W, 0402; AGILE_LINK: http://sj-agile9app/Agile/PLMServlet?action=OpenEmailObject&classid=10000&objid=146548997; IPN: A93548-034; Item Num: P02-11364R; LIFECYCLE_PHASE: Active; Lead Free Status: No; MFR_LIFECYCLE: Active; Manufacturer: Panasonic; Manufacturer Part Num: ERJ-2RKF1002X; Num Pins: 2; PART_SUBCLASS: RESISTORS; POWER: 1/16W; RoHS Compliant: Yes; TOLERANCE: +/-1%
R238 R239 R246 R248-R259 R834 = RES_0_OHM_5%_1_16W_0402_SMD: IPN: H30887-001
U17 = Si5341A-A-GM_1: IC -SILABS 5341A CLOCK CHIP FOR S10MX FPGA DK U16 (PRE-PROGRAMMED), ADDR 74H; IPN: K60224-001; Manufacturer: Silicon Laboratories
Y2 = CRYSTAL_SM_13: CRYSTAL - 48MHz +/-10ppm 8pF 23OHM -40°C ~ 85°C AEC-Q200 4-SMD DFN; IPN: K15539-001; Item Num: P07-19711R; Lead Free Status: Yes; MFR_LIFECYCLE: Active; Manufacturer: AVX Corp/Kyocera Corp; Manufacturer Part Num: CX3225SB48000D0FPJC1; Num Pins: 4; RoHS Compliant: Yes
C265 = CAP: CAP 1UF CER 10% 50VDC X5R 0603 SMT; AGILE_LINK: http://sj-agile9app/Agile/PLMServlet?action=OpenEmailObject&classid=10000&objid=256999866; IPN: H41388-001; Item Num: P03-17790R; LIFECYCLE_PHASE: Active; Lead Free Status: Lead Free; MFR_LIFECYCLE: Active; Manufacturer: Murata; Manufacturer Part Num: GRM188R61H105KAAL; Num Pins: 2; PART_SUBCLASS: CAPACITORS; RoHS Compliant: RoHS Compliant
C266 = CAP: CAP CER 0.1UF 25V 20% X7R 0402; IPN: K13660-001; Item Num: P03-17618R; LIFECYCLE_PHASE: Active; Manufacturer: TDK Electronics; Manufacturer Part Num: C1005X7R1E104M; Price: 0; RoHS Compliant: RoHS Compliant
C267 C270 = CAP: CAP, CERAMIC, 2.2UF, 10%, 10VDC, X5R, 0603; AGILE_LINK: http://sj-agile9app/Agile/PLMServlet?action=OpenEmailObject&classid=10000&objid=256999866; IPN: K13568-001; Item Num: P03-15213R; LIFECYCLE_PHASE: Active; Lead Free Status: Lead Free; MFR_LIFECYCLE: Active; Manufacturer: Murata; Manufacturer Part Num: GRM188R61A225KE34x; Num Pins: 2; PART_SUBCLASS: CAPACITORS; RATED_VOLTAGE: 10V; RoHS Compliant: RoHS Compliant; Supplier Part Num: 490-1545-1-ND; TOLERANCE: +/-10%
C268 C269 C271-C273 = CAP: CAP - CERAMIC, 0.22UF, 10V, X5R, 10%, 0402; AGILE_LINK: http://sj-agile9app/Agile/PLMServlet?action=OpenEmailObject&classid=10000&objid=257560276; IPN: G60984-001; Item Num: P03-15149R; LIFECYCLE_PHASE: Active; Lead Free Status: Not Lead Free; MFR_LIFECYCLE: Active; Manufacturer: Murata; Manufacturer Part Num: GRM155R61A224KE19D; Num Pins: 2; PART_SUBCLASS: CAPACITORS; RATED_VOLTAGE: 10V; RoHS Compliant: RoHS Compliant; TOLERANCE: +/-10%
R218-R226 = RESISTOR: RES 33 OHM 1/16W 5% 0402 SMD; IPN: K15753-001; Item Num: P02-14029R; LIFECYCLE_PHASE: Active; Manufacturer: Panasonic; Manufacturer Part Num: ERJ-2GEJ330X; RoHS Compliant: RoHS Compliant
R201-R204 R206 R208-R213 R227-R236 = RESISTOR: RES,10.0K OHMS,1.0%,1/16W, 0402; IPN: A93548-034; Item Num: P02-11364R; Manufacturer: Panasonic; Manufacturer Part Num: ERJ-2RKF1002X; Price: 0; RoHS Compliant: RoHS Compliant
U16 = MTFC8GAKAJCN-4M_IT: IC - eMMC,8GB,VFBGA-153; IPN: J73182-001; Item Num: P01-18101R; Manufacturer: Micron
U2 = FM6_2486A_V1.5: IPN: 99AH52
C274 = CAP: CAPC,Y5V,0402,0.1UF,25V,+80/-20%; AGILE_LINK: http://sj-agile9app/Agile/PLMServlet?action=OpenEmailObject&classid=10000&objid=213459527; IPN: K13560-001; Item Num: P03-15057R; LIFECYCLE_PHASE: Active; Lead Free Status: Lead Free; MFR_LIFECYCLE: Active; Manufacturer: Murata; Manufacturer Part Num: GRM155F51E104ZA01D; Num Pins: 2; PART_SUBCLASS: CAPACITORS; Part Class: CAPACITORS; RATED_VOLTAGE: 25V; RoHS Compliant: RoHS Compliant; TOLERANCE: +80%/-20%
C275-C283 C289-C292 C1201 C1219 C1220 C1448 C1449 = CAP: CAP - CER 1UF 6.3V 20% X5R 0201; IPN: C83410-013; Item Num: P03-17777R; Lead Free Status: Yes; Manufacturer: TDK; Manufacturer Part Num: C0603X5R0J105M; Num Pins: 2; Part Class: CAPACITORS; RoHS Compliant: Yes
C284-C287 C294-C297 = CAP: CAPC,Y5V,0402,0.1UF,25V,+80/-20%; Dielectric: Y5V; IPN: K13560-001; Item Num: P03-15057R; LIFECYCLE_PHASE: Active; Lead Free Status: Lead Free; MFR_LIFECYCLE: Active; Manufacturer: Murata; Manufacturer Part Num: GRM155F51E104ZA01D; Num Pins: 2; PART_SUBCLASS: CAPACITORS; Part Class: CAPACITORS; RATED_VOLTAGE: 25V; RoHS Compliant: RoHS Compliant; Tolerance: +80%/-20%
C1202 = CAP: CAP - CER, 4.7UF, 6.3V, X5R, 0603; AGILE_LINK: http://sj-agile9app/Agile/PLMServlet?action=OpenEmailObject&classid=10000&objid=257560276; IPN: G62544-001; Item Num: P03-16772R; LIFECYCLE_PHASE: Active; Lead Free Status: Not Lead Free; MFR_LIFECYCLE: Active; Manufacturer: Murata; Manufacturer Part Num: GRM188R60J475KE19D; Num Pins: 2; PART_SUBCLASS: CAPACITORS; RATED_VOLTAGE: 6.3V; RoHS Compliant: RoHS Compliant; TOLERANCE: +/-10%
C1450 = CAP: CAP - CER, 22UF, 16V, 20%, X5R, 0805; AGILE_LINK: http://sj-agile9app/Agile/PLMServlet?action=OpenEmailObject&classid=10000&objid=257560276; IPN: H14974-002; Item Num: P03-17664R; LIFECYCLE_PHASE: Active; Lead Free Status: Not Lead Free; MFR_LIFECYCLE: Active; Manufacturer: TDK Electronics; Manufacturer Part Num: GRM21BR61C226ME44L; Num Pins: 2; PART_SUBCLASS: CAPACITORS; RATED_VOLTAGE: 16V; RoHS Compliant: RoHS Compliant; TOLERANCE: +/-10%
FB9-FB11 FB16 FB38 = BEAD_FERRITE_SM: FERRITE BEAD 80 OHM 0805 1LN; IPN: G32678-001; Item Num: P04-17218R; LIFECYCLE_PHASE: Active; MFR_LIFECYCLE: Active; Manufacturer: Laird; Manufacturer Part Num: HI0805R800R-10; Num Pins: 2; PART_SUBCLASS: INDUCTORS; Part Class: Inductors; RoHS Compliant: Yes; Value2: 5A, 10mOhm
FB17 FB18 = BEAD_FERRITE_SM: FERRITE BEAD 22 OHM 0603; IPN: M16845-001; Item Num: M16845-001; LIFECYCLE_PHASE: Active; MFR_LIFECYCLE: Active; Manufacturer: Murata; Manufacturer Part Num: BLM18SN220TZ1D; Num Pins: 2; PART_SUBCLASS: INDUCTORS; Part Class: Inductors; RoHS Compliant: Yes
C258-C260 C262 C263 = CAP: CAP CER 0.1UF 25V 20% X7R 0402; IPN: K13660-001; Item Num: P03-17618R; Manufacturer: TDK Electronics; Manufacturer Part Num: C1005X7R1E104M; RoHS Compliant: RoHS Compliant
C261 C264 = CAP: CAP, CERAMIC, 2.2UF, 10%, 10VDC, X5R, 0603; IPN: K13568-001; Item Num: P03-15213R; Manufacturer: Murata; Manufacturer Part Num: GRM188R61A225KE34x; RoHS Compliant: RoHS Compliant
D4-D6 = ESD_DIODE_DUAL: DIODE - ULTRA LOW CAPACITANCE ESD DIODE ARRAY; Device: D11; IPN: H25612-001; Item Num: P08-20821R; MFR_LIFECYCLE: Active; Manufacturer: Infineon; Manufacturer Part Num: ESD5V3U2U-03LRH E6327; RoHS Compliant: RoHS Compliant
J11 = SD_SKT_1: CONN-MICRO SD CARD SOCKET; IPN: K12160-001; Item Num: P23-38481R; MFR_LIFECYCLE: Active; Manufacturer: Wurth Elektroniks; Manufacturer Part Num: 693071010811; RoHS Compliant: RoHS Compliant
J12 = 2-767004-2: 38PIN MICTOR HEADER; Item Num: P23-08655R; Manufacturer: AMP/Tyco (Tyco Electronics Corporation); Mfr Code: AMTY; Price: 11.22; RoHS Compliant: RoHS Compliant
R180 = RESISTOR: RES - 200K OHM, 1/16W, 1%, 0402 SMD; IPN: A93548-186; Item Num: P02-15992R; Lead Free Status: No; Manufacturer: Panasonic; Manufacturer Part Num: ERJ-2RKF2003X; Num Pins: 2; Part Class: RESISTORS; Price: 0; RoHS Compliant: RoHS Compliant
R181-R186 R214-R217 = RESISTOR: RES,1.00K OHMS,1.0%,1/16W,0402; IPN: G60609-021; Item Num: P02-11372R; Manufacturer: Panasonic; Manufacturer Part Num: ERJ-2RKF1001X; Num Pins: 2; RoHS Compliant: RoHS Compliant
R187 = RESISTOR: RES ZERO OHM 1/16W 5% 0402 SMD; IPN: H30887-001; Item Num: P02-14020R; Manufacturer: Panasonic; Manufacturer Part Num: ERJ-2GE0R00X; Num Pins: 2; RoHS Compliant: RoHS Compliant
R188 = RESISTOR: RES 0.1 OHM 1% 1/2W 0805 SMD; IPN: K16286-001; Item Num: P02-17735R; Lead Free Status: Yes; Manufacturer: Panasonic; Manufacturer Part Num: ERJ6BWFR100V; Num Pins: 2; Part Class: Resistors; Price: 0; RoHS Compliant: Yes
R189 R191-R193 = RESISTOR: RES - 499OHM, 1% 0603 1/10W; IPN: K16586-001; Item Num: P02-14004R; Manufacturer: Panasonic; Manufacturer Part Num: ERJ-3EKF4990V; Num Pins: 2; PART_SUBCLASS: RESISTORS; Part Class: Resistors; RoHS Compliant: Yes
R190 = RESISTOR: RES,4.70K OHMS,1.0%,1/16W,0402; IPN: D60468-001; Item Num: P02-11384R; LIFECYCLE_PHASE: Active; Manufacturer: Vishay; Manufacturer Part Num: CRCW04024K70FKED; RoHS Compliant: RoHS Compliant
R194 R195 = RESISTOR: RES - ANTI-SULFER, 330 OHM, 1%, 1/10W, 0603; IPN: K16221-001; Item Num: P02-16628R; Manufacturer: Panasonic; Manufacturer Part Num: ERJ-S03F3300V; Num Pins: 2; PART_SUBCLASS: RESISTORS; Part Class: Resistors; RoHS Compliant: Yes
R196 = RESISTOR: RES - 470K OHM, 1/16W, 1%, 0402 SMD; IPN: A93548-659; Item Num: P02-14607R; LIFECYCLE_PHASE: Active; Lead Free Status: No; Manufacturer: Vishay; Manufacturer Part Num: CRCW0402470KFKED; Num Pins: 2; RoHS Compliant: RoHS Compliant
R197-R200 = RESISTOR: RES ZERO OHM 1/16W 5% 0402 SMD; Altera Part No.: P02-14020R; IPN: H30887-001; Item Num: P02-14020R; Lead Free Status: No; Manufacturer: Panasonic; Manufacturer Part Num: ERJ-2GE0R00X; Num Pins: 2; Part Class: RESISTORS; RoHS Compliant: Yes; Tolerance: 5%
R205 R207 = RESISTOR: RES - 0 OHM, 5% 0603 1/10W; IPN: E57868-001; Item Num: P02-14007R; MFR_LIFECYCLE: Active; Manufacturer: Panasonic; Manufacturer Part Num: ERJ-3GEY0R00V; Num Pins: 2; RoHS Compliant: RoHS Compliant
U14 = LSF0108PWR: 8 CHANNEL BIDIRECTIONAL MULTI-VOLTAGE LEVEL TRANSLATOR; IPN: H73147-001; Item Num: P01-18018R; Manufacturer: TI; RoHS Compliant: RoHS Compliant
U15 = TPS22902BYFPR: IPN: J40426-001; Manufacturer: TI

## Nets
GND: C258.1 C259.1 C260.1 C261.2 C262.1 C263.1 C264.2 C265.2 C266.1 C267.2 C268.2 C269.2 C270.2 C271.2 C272.2 C273.2 C275.2 C276.2 C277.2 C278.2 C279.2 C280.2 C281.2 C282.2 C283.2 C284.2 C285.2 C286.2 C287.2 C289.2 C290.2 C291.2 C292.2 C294.2 C295.2 C296.2 C297.2 C298.2 C299.2 C300.2 C301.2 C302.2 C303.2 C304.2 C305.2 C306.2 C307.2 C308.2 C309.2 C310.2 C311.2 C312.2 C313.2 C314.2 C1201.2 C1202.2 C1219.2 C1220.2 C1448.2 C1449.2 C1450.2 D4.3(A) D5.3(A) D6.3(A) J11.6(VSS) J11.9(CAGE) J11.10(CAGE) J11.11(CAGE) J11.12(CAGE) J12.5(GND) J12.16(TD7) J12.18(TD6) J12.20(TD5) J12.22(TD4) J12.23(TD15) J12.24(TD3) J12.25(TD14) J12.26(TD2) J12.27(TD13) J12.28(TD1) J12.29(TD12) J12.31(TD11) J12.33(TD10) J12.35(TD9) J12.37(TD8) J12.38(TD0) J12.39(GND1) J12.40(GND2) J12.41(GND3) J12.42(GND4) J12.43(GND5) R196.1 R201.1 R202.2 R203.1 R204.1 R206.2 R208.1 R209.1 R211.1 R217.1 R241.2 R242.2 U2.A2(GND) U2.A4(GND) U2.A18(GND) U2.A32(GND) U2.A46(GND) U2.A58(GND) U2.A60(GND) U2.AA40(GND) U2.AA50(GND) U2.AA54(GND) U2.AA58(GND) U2.AA60(GND) U2.AB21(GND) U2.AB41(GND) U2.AB49(GND) U2.AB51(GND) U2.AB53(GND) U2.AB57(GND) U2.AB59(GND) U2.AC20(GND) U2.AC24(GND) U2.AC26(GND) U2.AC28(GND) U2.AC30(GND) U2.AC32(GND) U2.AC34(GND) U2.AC36(GND) U2.AC38(GND) U2.AC40(GND) U2.AC48(GND) U2.AC50(GND) U2.AC52(GND) U2.AC54(GND) U2.AC58(GND) U2.AC60(GND) U2.AD41(GND) U2.AD47(GND) U2.AD51(GND) U2.AD55(GND) U2.AD57(GND) U2.AD61(GND) U2.AE2(GND) U2.AE4(GND) U2.AE6(GND) U2.AE8(GND) U2.AE10(GND) U2.AE12(GND) U2.AE14(GND) U2.AE16(GND) U2.AE18(GND) U2.AE20(GND) U2.AE22(GND) U2.AE24(GND) U2.AE26(GND) U2.AE28(GND) U2.AE30(GND) U2.AE32(GND) U2.AE34(GND) U2.AE36(GND) U2.AE38(GND) U2.AE40(GND) U2.AE42(GND) U2.AE46(GND) U2.AE50(GND) U2.AE54(GND) U2.AE56(GND) U2.AE60(GND) U2.AE62(GND) U2.AF11(GND) U2.AF13(GND) U2.AF15(GND) U2.AF17(GND) U2.AF39(GND) U2.AF45(GND) U2.AF47(GND) U2.AF49(GND) U2.AF51(GND) U2.AF53(GND) U2.AF57(GND) U2.AF59(GND) U2.AG2(GND) U2.AG8(GND) U2.AG10(GND) U2.AG12(GND) U2.AG14(GND) U2.AG16(GND) U2.AG18(GND) U2.AG20(GND) U2.AG22(GND) U2.AG24(GND) U2.AG26(GND) U2.AG28(GND) U2.AG30(GND) U2.AG32(GND) U2.AG34(GND) U2.AG36(GND) U2.AG38(GND) U2.AG40(GND) U2.AG42(GND) U2.AG44(GND) U2.AG48(GND) U2.AG50(GND) U2.AG52(GND) U2.AG54(GND) U2.AG58(GND) U2.AG60(GND) U2.AH1(GND) U2.AH3(GND) U2.AH7(GND) U2.AH9(GND) U2.AH39(GND) U2.AH47(GND) U2.AH51(GND) U2.AH55(GND) U2.AH57(GND) U2.AH61(GND) U2.AJ4(GND) U2.AJ6(GND) U2.AJ10(GND) U2.AJ18(GND) U2.AJ22(GND) U2.AJ38(GND) U2.AJ40(GND) U2.AJ42(GND) U2.AJ44(GND) U2.AJ50(GND) U2.AJ54(GND) U2.AJ56(GND) U2.AJ60(GND) U2.AJ62(GND) U2.AK3(GND) U2.AK5(GND) U2.AK9(GND) U2.AK11(GND) U2.AK19(GND) U2.AK43(GND) U2.AK45(GND) U2.AK47(GND) U2.AK49(GND) U2.AK51(GND) U2.AK53(GND) U2.AK57(GND) U2.AK59(GND) U2.AL2(GND) U2.AL6(GND) U2.AL8(GND) U2.AL12(GND) U2.AL18(GND) U2.AL20(GND) U2.AL22(GND) U2.AL24(GND) U2.AL26(GND) U2.AL28(GND) U2.AL30(GND) U2.AL32(GND) U2.AL34(GND) U2.AL36(GND) U2.AL38(GND) U2.AL40(GND) U2.AL42(GND) U2.AL44(GND) U2.AL46(GND) U2.AL48(GND) U2.AL50(GND) U2.AL52(GND) U2.AL54(GND) U2.AL58(GND) U2.AL60(GND) U2.AM1(GND) U2.AM3(GND) U2.AM7(GND) U2.AM9(GND) U2.AM13(GND) U2.AM15(GND) U2.AM17(GND) U2.AM43(GND) U2.AM45(GND) U2.AM47(GND) U2.AM51(GND) U2.AM55(GND) U2.AM57(GND) U2.AM61(GND) U2.AN4(GND) U2.AN6(GND) U2.AN10(GND) U2.AN12(GND) U2.AN22(GND) U2.AN24(GND) U2.AN26(GND) U2.AN28(GND) U2.AN30(GND) U2.AN32(GND) U2.AN34(GND) U2.AN36(GND) U2.AN38(GND) U2.AN40(GND) U2.AN42(GND) U2.AN44(GND) U2.AN50(GND) U2.AN54(GND) U2.AN56(GND) U2.AN60(GND) U2.AN62(GND) U2.AP3(GND) U2.AP5(GND) U2.AP9(GND) U2.AP11(GND) U2.AP15(GND) U2.AP19(GND) U2.AP43(GND) U2.AP45(GND) U2.AP47(GND) U2.AP51(GND) U2.AP53(GND) U2.AP57(GND) U2.AP59(GND) U2.AR2(GND) U2.AR6(GND) U2.AR8(GND) U2.AR12(GND) U2.AR22(GND) U2.AR24(GND) U2.AR26(GND) U2.AR38(GND) U2.AR40(GND) U2.AR42(GND) U2.AR46(GND) U2.AR50(GND) U2.AR52(GND) U2.AR54(GND) U2.AR58(GND) U2.AR60(GND) U2.AT1(GND) U2.AT3(GND) U2.AT7(GND) U2.AT9(GND) U2.AT15(GND) U2.AT43(GND) U2.AT45(GND) U2.AT47(GND) U2.AT51(GND) U2.AT55(GND) U2.AT57(GND) U2.AT61(GND) U2.AU4(GND) U2.AU6(GND) U2.AU10(GND) U2.AU12(GND) U2.AU14(GND) U2.AU16(GND) U2.AU18(GND) U2.AU22(GND) U2.AU24(GND) U2.AU26(GND) U2.AU38(GND) U2.AU40(GND) U2.AU42(GND) U2.AU48(GND) U2.AU50(GND) U2.AU54(GND) U2.AU56(GND) U2.AU60(GND) U2.AU62(GND) U2.AV3(GND) U2.AV5(GND) U2.AV9(GND) U2.AV11(GND) U2.AV13(GND) U2.AV17(GND) U2.AV19(GND) U2.AV45(GND) U2.AV51(GND) U2.AV53(GND) U2.AV57(GND) U2.AV59(GND) U2.AW2(GND) U2.AW6(GND) U2.AW8(GND) U2.AW12(GND) U2.AW16(GND) U2.AW18(GND) U2.AW22(GND) U2.AW24(GND) U2.AW26(GND) U2.AW38(GND) U2.AW40(GND) U2.AW42(GND) U2.AW48(GND) U2.AW50(GND) U2.AW52(GND) U2.AW54(GND) U2.AW58(GND) U2.AW60(GND) U2.AY1(GND) U2.AY3(GND) U2.AY7(GND) U2.AY9(GND) U2.AY13(GND) U2.AY45(GND) U2.AY51(GND) U2.AY55(GND) U2.AY57(GND) U2.AY61(GND) U2.B1(GND) U2.B3(GND) U2.B11(GND) U2.B25(GND) U2.B39(GND) U2.B53(GND) U2.B59(GND) U2.B61(GND) U2.BA4(GND) U2.BA6(GND) U2.BA10(GND) U2.BA12(GND) U2.BA16(GND) U2.BA18(GND) U2.BA20(GND) U2.BA22(GND) U2.BA24(GND) U2.BA38(GND) U2.BA40(GND) U2.BA42(GND) U2.BA46(GND) U2.BA48(GND) U2.BA50(GND) U2.BA54(GND) U2.BA56(GND) U2.BA60(GND) U2.BA62(GND) U2.BB3(GND) U2.BB5(GND) U2.BB9(GND) U2.BB11(GND) U2.BB13(GND) U2.BB43(GND) U2.BB45(GND) U2.BB47(GND) U2.BB51(GND) U2.BB53(GND) U2.BB57(GND) U2.BB59(GND) U2.BC2(GND) U2.BC6(GND) U2.BC8(GND) U2.BC12(GND) U2.BC16(GND) U2.BC18(GND) U2.BC22(GND) U2.BC24(GND) U2.BC26(GND) U2.BC38(GND) U2.BC40(GND) U2.BC42(GND) U2.BC50(GND) U2.BC52(GND) U2.BC54(GND) U2.BC58(GND) U2.BC60(GND) U2.BD1(GND) U2.BD3(GND) U2.BD7(GND) U2.BD9(GND) U2.BD13(GND) U2.BD15(GND) U2.BD17(GND) U2.BD45(GND) U2.BD47(GND) U2.BD51(GND) U2.BD55(GND) U2.BD57(GND) U2.BD61(GND) U2.BE4(GND) U2.BE6(GND) U2.BE10(GND) U2.BE12(GND) U2.BE18(GND) U2.BE22(GND) U2.BE24(GND) U2.BE26(GND) U2.BE38(GND) U2.BE40(GND) U2.BE42(GND) U2.BE48(GND) U2.BE50(GND) U2.BE54(GND) U2.BE56(GND) U2.BE60(GND) U2.BE62(GND) U2.BF3(GND) U2.BF5(GND) U2.BF9(GND) U2.BF11(GND) U2.BF13(GND) U2.BF15(GND) U2.BF17(GND) U2.BF19(GND) U2.BF45(GND) U2.BF47(GND) U2.BF49(GND) U2.BF51(GND) U2.BF53(GND) U2.BF57(GND) U2.BF59(GND) U2.BG2(GND) U2.BG6(GND) U2.BG8(GND) U2.BG12(GND) U2.BG18(GND) U2.BG20(GND) U2.BG22(GND) U2.BG24(GND) U2.BG26(GND) U2.BG38(GND) U2.BG40(GND) U2.BG42(GND) U2.BG44(GND) U2.BG46(GND) U2.BG48(GND) U2.BG50(GND) U2.BG52(GND) U2.BG54(GND) U2.BG58(GND) U2.BG60(GND) U2.BH1(GND) U2.BH3(GND) U2.BH7(GND) U2.BH9(GND) U2.BH13(GND) U2.BH15(GND) U2.BH17(GND) U2.BH51(GND) U2.BH55(GND) U2.BH57(GND) U2.BH61(GND) U2.BJ4(GND) U2.BJ6(GND) U2.BJ10(GND) U2.BJ12(GND) U2.BJ16(GND) U2.BJ18(GND) U2.BJ22(GND) U2.BJ24(GND) U2.BJ26(GND) U2.BJ38(GND) U2.BJ40(GND) U2.BJ42(GND) U2.BJ44(GND) U2.BJ46(GND) U2.BJ48(GND) U2.BJ50(GND) U2.BJ54(GND) U2.BJ56(GND) U2.BJ60(GND) U2.BJ62(GND) U2.BK3(GND) U2.BK5(GND) U2.BK9(GND) U2.BK11(GND) U2.BK13(GND) U2.BK43(GND) U2.BK45(GND) U2.BK47(GND) U2.BK51(GND) U2.BK53(GND) U2.BK57(GND) U2.BK59(GND) U2.BL2(GND) U2.BL6(GND) U2.BL8(GND) U2.BL12(GND) U2.BL16(GND) U2.BL18(GND) U2.BL22(GND) U2.BL24(GND) U2.BL26(GND) U2.BL28(GND) U2.BL30(GND) U2.BL32(GND) U2.BL34(GND) U2.BL36(GND) U2.BL38(GND) U2.BL40(GND) U2.BL42(GND) U2.BL52(GND) U2.BL54(GND) U2.BL58(GND) U2.BL60(GND) U2.BM1(GND) U2.BM3(GND) U2.BM7(GND) U2.BM9(GND) U2.BM13(GND) U2.BM19(GND) U2.BM51(GND) U2.BM55(GND) U2.BM57(GND) U2.BM61(GND) U2.BN4(GND) U2.BN6(GND) U2.BN10(GND) U2.BN12(GND) U2.BN16(GND) U2.BN18(GND) U2.BN20(GND) U2.BN22(GND) U2.BN24(GND) U2.BN26(GND) U2.BN28(GND) U2.BN30(GND) U2.BN32(GND) U2.BN34(GND) U2.BN36(GND) U2.BN38(GND) U2.BN40(GND) U2.BN42(GND) U2.BN48(DNU50) U2.BN54(GND) U2.BN56(GND) U2.BN60(GND) U2.BN62(GND) U2.BP3(GND) U2.BP5(GND) U2.BP9(GND) U2.BP11(GND) U2.BP13(GND) U2.BP43(GND) U2.BP45(GND) U2.BP49(GND) U2.BP51(GND) U2.BP53(GND) U2.BP57(GND) U2.BP59(GND) U2.BR2(GND) U2.BR6(GND) U2.BR8(GND) U2.BR12(GND) U2.BR14(GND) U2.BR16(GND) U2.BR18(GND) U2.BR22(GND) U2.BR38(GND) U2.BR40(GND) U2.BR42(GND) U2.BR46(GND) U2.BR48(GND) U2.BR52(GND) U2.BR54(GND) U2.BR58(GND) U2.BR60(GND) U2.BT1(GND) U2.BT3(GND) U2.BT7(GND) U2.BT9(GND) U2.BT13(GND) U2.BT15(GND) U2.BT17(GND) U2.BT25(GND) U2.BT55(GND) U2.BT57(GND) U2.BT61(GND) U2.BU4(GND) U2.BU6(GND) U2.BU10(GND) U2.BU12(GND) U2.BU18(GND) U2.BU20(GND) U2.BU22(GND) U2.BU24(GND) U2.BU26(GND) U2.BU28(GND) U2.BU30(GND) U2.BU32(GND) U2.BU34(GND) U2.BU36(GND) U2.BU38(GND) U2.BU40(GND) U2.BU42(GND) U2.BU54(DNU52) U2.BU56(GND) U2.BU62(GND) U2.BV3(GND) U2.BV5(GND) U2.BV9(GND) U2.BV11(GND) U2.BV25(GND) U2.BV57(DNU51) U2.BV59(GND) U2.BV61(GND) U2.BW2(GND) U2.BW6(GND) U2.BW8(GND) U2.BW12(GND) U2.BW14(GND) U2.BW16(GND) U2.BW20(GND) U2.BW22(GND) U2.BW24(GND) U2.BW26(GND) U2.BW28(GND) U2.BW30(GND) U2.BW32(GND) U2.BW34(GND) U2.BW36(GND) U2.BW38(GND) U2.BW40(GND) U2.BW42(GND) U2.BW44(GND) U2.BW46(GND) U2.BW48(GND) U2.BW50(GND) U2.BW52(GND) U2.BW54(GND) U2.BW56(GND) U2.BW58(GND) U2.BW60(GND) U2.BW62(GND) U2.BY1(GND) U2.BY3(GND) U2.BY7(GND) U2.BY9(GND) U2.BY13(GND) U2.BY23(GND) U2.BY51(GND) U2.C2(GND) U2.C4(GND) U2.C18(GND) U2.C32(GND) U2.C46(GND) U2.C60(GND) U2.C62(GND) U2.CA2(GND) U2.CA4(GND) U2.CA6(GND) U2.CA8(GND) U2.CA10(GND) U2.CA12(GND) U2.CA20(GND) U2.CA22(GND) U2.CA24(GND) U2.CA26(GND) U2.CA28(GND) U2.CA30(GND) U2.CA32(GND) U2.CA34(GND) U2.CA36(GND) U2.CA38(GND) U2.CA40(GND) U2.CA42(GND) U2.CA44(GND) U2.CA46(GND) U2.CB3(GND) U2.CB5(GND) U2.CB9(GND) U2.CB11(GND) U2.CB23(GND) U2.CB55(GND) U2.CC4(GND) U2.CC6(GND) U2.CC10(GND) U2.CC12(GND) U2.CC40(GND) U2.CC42(GND) U2.CC44(GND) U2.CC46(GND) U2.CC54(GND) U2.CD1(GND) U2.CD3(GND) U2.CD5(GND) U2.CD7(GND) U2.CD9(GND) U2.CD11(GND) U2.CD13(GND) U2.CD15(GND) U2.CD17(GND) U2.CD19(GND) U2.CD21(GND) U2.CD23(GND) U2.CD25(GND) U2.CD27(GND) U2.CD29(GND) U2.CD31(GND) U2.CD33(GND) U2.CD35(GND) U2.CD37(GND) U2.CD39(GND) U2.CD41(GND) U2.CD43(GND) U2.CD45(GND) U2.CD47(GND) U2.CD49(GND) U2.CD51(GND) U2.CD53(GND) U2.CD55(GND) U2.CD57(GND) U2.CD59(GND) U2.CD61(GND) U2.CE2(GND) U2.CE16(GND) U2.CE30(GND) U2.CE44(GND) U2.CE58(GND) U2.CF9(GND) U2.CF23(GND) U2.CF37(GND) U2.CF51(GND) U2.CG2(GND) U2.CG16(GND) U2.CG30(GND) U2.CG44(GND) U2.CG58(GND) U2.CH9(GND) U2.CH23(GND) U2.CH37(GND) U2.CH51(GND) U2.CJ2(GND) U2.CJ4(GND) U2.CJ6(GND) U2.CJ8(GND) U2.CJ10(GND) U2.CJ12(GND) U2.CJ14(GND) U2.CJ16(GND) U2.CJ18(GND) U2.CJ20(GND) U2.CJ22(GND) U2.CJ24(GND) U2.CJ26(GND) U2.CJ28(GND) U2.CJ30(GND) U2.CJ32(GND) U2.CJ34(GND) U2.CJ36(GND) U2.CJ38(GND) U2.CJ40(GND) U2.CJ42(GND) U2.CJ44(GND) U2.CJ46(GND) U2.CJ48(GND) U2.CJ50(GND) U2.CJ52(GND) U2.CJ54(GND) U2.CJ56(GND) U2.CJ58(GND) U2.CJ60(GND) U2.CJ62(GND) U2.CK9(GND) U2.CK23(GND) U2.CK37(GND) U2.CK51(GND) U2.CL2(GND) U2.CL16(GND) U2.CL30(GND) U2.CL44(GND) U2.CL58(GND) U2.CM9(GND) U2.CM23(GND) U2.CM37(GND) U2.CM51(GND) U2.CN2(GND) U2.CN16(GND) U2.CN30(GND) U2.CN44(GND) U2.CN58(GND) U2.CP1(GND) U2.CP3(GND) U2.CP5(GND) U2.CP7(GND) U2.CP9(GND) U2.CP11(GND) U2.CP13(GND) U2.CP15(GND) U2.CP17(GND) U2.CP19(GND) U2.CP21(GND) U2.CP23(GND) U2.CP25(GND) U2.CP27(GND) U2.CP29(GND) U2.CP31(GND) U2.CP33(GND) U2.CP35(GND) U2.CP37(GND) U2.CP39(GND) U2.CP41(GND) U2.CP43(GND) U2.CP45(GND) U2.CP47(GND) U2.CP49(GND) U2.CP51(GND) U2.CP53(GND) U2.CP55(GND) U2.CP57(GND) U2.CP59(GND) U2.CP61(GND) U2.CR2(GND) U2.CR16(GND) U2.CR30(GND) U2.CR44(GND) U2.CR58(GND) U2.CT9(GND) U2.CT23(GND) U2.CT37(GND) U2.CT51(GND) U2.CU2(GND) U2.CU16(GND) U2.CU30(GND) U2.CU44(GND) U2.CU58(GND) U2.CV9(GND) U2.CV23(GND) U2.CV37(GND) U2.CV51(GND) U2.CW2(GND) U2.CW4(GND) U2.CW6(GND) U2.CW8(GND) U2.CW10(GND) U2.CW12(GND) U2.CW14(GND) U2.CW16(GND) U2.CW18(GND) U2.CW20(GND) U2.CW22(GND) U2.CW24(GND) U2.CW26(GND) U2.CW28(GND) U2.CW30(GND) U2.CW32(GND) U2.CW34(GND) U2.CW36(GND) U2.CW38(GND) U2.CW40(GND) U2.CW42(GND) U2.CW44(GND) U2.CW46(GND) U2.CW48(GND) U2.CW50(GND) U2.CW52(GND) U2.CW54(GND) U2.CW56(GND) U2.CW58(GND) U2.CW60(GND) U2.CW62(GND) U2.CY1(GND) U2.CY9(GND) U2.CY23(GND) U2.CY37(GND) U2.CY51(GND) U2.CY61(GND) U2.D1(GND) U2.D3(GND) U2.D11(GND) U2.D25(GND) U2.D39(GND) U2.D53(GND) U2.D61(GND) U2.DA2(GND) U2.DA16(GND) U2.DA30(GND) U2.DA44(GND) U2.DA58(GND) U2.DA60(GND) U2.DA62(GND) U2.DB1(GND) U2.DB3(GND) U2.DB9(GND) U2.DB23(GND) U2.DB37(GND) U2.DB51(GND) U2.DB59(GND) U2.DB61(GND) U2.DC2(GND) U2.DC4(GND) U2.DC16(GND) U2.DC30(GND) U2.DC44(GND) U2.DC58(GND) U2.DC60(GND) U2.E2(GND) U2.E4(GND) U2.E6(GND) U2.E8(GND) U2.E10(GND) U2.E12(GND) U2.E14(GND) U2.E16(GND) U2.E18(GND) U2.E20(GND) U2.E22(GND) U2.E24(GND) U2.E26(GND) U2.E28(GND) U2.E30(GND) U2.E32(GND) U2.E34(GND) U2.E36(GND) U2.E38(GND) U2.E40(GND) U2.E42(GND) U2.E44(GND) U2.E46(GND) U2.E48(GND) U2.E50(GND) U2.E52(GND) U2.E54(GND) U2.E56(GND) U2.E58(GND) U2.E60(GND) U2.E62(GND) U2.F11(GND) U2.F25(GND) U2.F39(GND) U2.F53(GND) U2.G4(GND) U2.G18(GND) U2.G32(GND) U2.G46(GND) U2.G60(GND) U2.H11(GND) U2.H25(GND) U2.H39(GND) U2.H53(GND) U2.J4(GND) U2.J18(GND) U2.J32(GND) U2.J46(GND) U2.J60(GND) U2.K1(GND) U2.K3(GND) U2.K5(GND) U2.K7(GND) U2.K9(GND) U2.K11(GND) U2.K13(GND) U2.K15(GND) U2.K17(GND) U2.K19(GND) U2.K21(GND) U2.K23(GND) U2.K25(GND) U2.K27(GND) U2.K29(GND) U2.K31(GND) U2.K33(GND) U2.K35(GND) U2.K37(GND) U2.K39(GND) U2.K41(GND) U2.K43(GND) U2.K45(GND) U2.K47(GND) U2.K49(GND) U2.K51(GND) U2.K53(GND) U2.K55(GND) U2.K57(GND) U2.K59(GND) U2.K61(GND) U2.L4(GND) U2.L18(GND) U2.L32(GND) U2.L46(GND) U2.L60(GND) U2.M11(GND) U2.M25(GND) U2.M39(GND) U2.M53(GND) U2.N4(GND) U2.N18(GND) U2.N32(GND) U2.N46(GND) U2.N60(GND) U2.P11(GND) U2.P25(GND) U2.P39(GND) U2.P53(GND) U2.R2(GND) U2.R4(GND) U2.R6(GND) U2.R8(GND) U2.R10(GND) U2.R12(GND) U2.R14(GND) U2.R16(GND) U2.R18(GND) U2.R20(GND) U2.R22(GND) U2.R24(GND) U2.R26(GND) U2.R28(GND) U2.R30(GND) U2.R32(GND) U2.R34(GND) U2.R36(GND) U2.R38(GND) U2.R40(GND) U2.R42(GND) U2.R44(GND) U2.R46(GND) U2.R48(GND) U2.R50(GND) U2.R52(GND) U2.R54(GND) U2.R56(GND) U2.R58(GND) U2.R60(GND) U2.R62(GND) U2.T11(GND) U2.T25(GND) U2.T39(GND) U2.T53(GND) U2.U4(GND) U2.U18(GND) U2.U32(GND) U2.U46(GND) U2.U60(GND) U2.V11(GND) U2.V25(GND) U2.V39(GND) U2.V53(GND) U2.W4(GND) U2.W18(GND) U2.W32(GND) U2.W46(GND) U2.W60(GND) U2.Y1(GND) U2.Y3(GND) U2.Y5(GND) U2.Y7(GND) U2.Y9(GND) U2.Y11(GND) U2.Y13(GND) U2.Y15(GND) U2.Y17(GND) U2.Y19(GND) U2.Y21(GND) U2.Y23(GND) U2.Y25(GND) U2.Y27(GND) U2.Y29(GND) U2.Y31(GND) U2.Y33(GND) U2.Y35(GND) U2.Y37(GND) U2.Y39(GND) U2.Y41(GND) U2.Y43(GND) U2.Y45(GND) U2.Y47(GND) U2.Y49(GND) U2.Y51(GND) U2.Y53(GND) U2.Y55(GND) U2.Y57(GND) U2.Y59(GND) U2.Y61(GND) U14.1(GND) U15.B1(GND) U16.A6(VSS1) U16.C4(VSSQ1) U16.D4(NC33) U16.E7(VSS2) U16.G5(VSS3) U16.H10(VSS4) U16.J5(VSS5) U16.K8(VSS6) U16.N1(NC90) U16.N2(VSSQ2) U16.N5(VSSQ3) U16.P4(VSSQ4) U16.P6(VSSQ5) U17.65(ePAD) ; also on sheet 9 11 12 13 14 15 17 18 20 21 22 23 24 25 26 28 29 39 40 41 42 43 44 45 46 47 48 49 50 51 52 53 54 55 56 57 58 59 60 61 62 63 64 65 66
GNDSENSE: C274.1 R239.1 U2.BA26(GNDSENSE)
VCC_SENSE: R238.2 ; also on sheet 51 52
VCCA_PLL: FB17.2 FB18.2 ; also on sheet 45
VCCA_PLL_FLTR: FB17.1 FB18.1 U2.AA28(VCCA_PLL) U2.AA30(VCCA_PLL) U2.AA32(VCCA_PLL) U2.AA34(VCCA_PLL) U2.CC28(VCCA_PLL) U2.CC30(VCCA_PLL) U2.CC32(VCCA_PLL) U2.CC34(VCCA_PLL) ; also on sheet 45 65
VCCCLK_GXPL1: C275.1 C276.1 FB38.1 U2.BH45(VCCCLK_GXPL1) U2.BH47(VCCCLK_GXPL1)
VCCFUSE_GXP: C1201.1 C1202.1 FB12.1 FB13.1 U2.BR44(VCCFUSE_GXP)
VCCFUSEWR_SDM: U2.BY49(VCCFUSEWR_SDM) U2.CB49(VCCFUSEWR_SDM) ; also on sheet 64 65
VCCH_GXPL1: FB11.2 U2.AN46(VCCH_GXPL1) U2.AU46(VCCH_GXPL1) U2.AV47(VCCH_GXPL1) U2.AW46(VCCH_GXPL1) U2.AY47(VCCH_GXPL1) U2.BC46(VCCH_GXPL1) U2.BE46(VCCH_GXPL1) ; also on sheet 65
VCCLSENSE: C274.2 R238.1 U2.BB25(VCCLSENSE)
VCCPLL_HPS: C291.1 C292.1 FB14.2 U2.AA22(VCCPLL_HPS) U2.AC22(VCCPLL_HPS)
VCCPLL_SDM: C289.1 C290.1 FB15.2 U2.BY47(VCCPLL_SDM) U2.CB47(VCCPLL_SDM)
VCCPLLDIG_HPS: C278.1 C279.1 FB10.1 U2.AB23(VCCPLLDIG_HPS) U2.AD23(VCCPLLDIG_HPS)
VCCPLLDIG_SDM: C280.1 C281.1 FB9.1 U2.BY45(VCCPLLDIG_SDM) U2.CB45(VCCPLLDIG_SDM)
VCCRTPLL_GXER1: C282.1 C283.1 C1448.1 C1449.1 C1450.1 FB16.1 U2.BE16(VCCRTPLL_GXER1) U2.BG16(VCCRTPLL_GXER1)
VDDIM: C265.1 C266.2 U16.C1(NC19) U16.C2(VDDIM)
VSS_SENSE: R239.2 ; also on sheet 51 52
0p6V_VREF_DDR4_CH01: C284.1 C285.1 C286.1 C287.1 U2.AA24(VREFB3DN0) U2.AA26(VREFB3CN0) U2.AA36(VREFB3BN0) U2.AA38(VREFB3AN0) ; also on sheet 9 12 62
0p6V_VREF_DDR4_CH23: C294.1 C295.1 C296.1 C297.1 U2.CC24(VREFB2DN0) U2.CC26(VREFB2CN0) U2.CC36(VREFB2BN0) U2.CC38(VREFB2AN0) ; also on sheet 15 18 62
0p8V_VCCL_SDM: FB9.2 U2.BT39(VCCL_SDM) U2.BT41(VCCL_SDM) U2.BV39(VCCL_SDM) U2.BV41(VCCL_SDM) ; also on sheet 46 55 65
0p9V_VCCH: FB13.2 FB16.2 U2.AR44(VCC_HSSI_GXPL1) U2.AU20(VCC_HSSI_GXER1) U2.AU44(VCC_HSSI_GXPL1) U2.AV43(VCCH) U2.AW20(VCC_HSSI_GXER1) U2.AW44(VCC_HSSI_GXPL1) U2.AY19(VCC_HSSI_GXER1) U2.AY43(VCCH) U2.BA44(VCC_HSSI_GXPL1) U2.BB19(VCC_HSSI_GXER1) U2.BC20(VCCH) U2.BC44(VCC_HSSI_GXPL1) U2.BD19(VCC_HSSI_GXER1) U2.BD43(VCCH) U2.BE20(VCCH) U2.BE44(VCC_HSSI_GXPL1) U2.BF43(VCCH) U2.BH19(VCC_HSSI_GXER1) U2.BH43(VCC_HSSI_GXPL1) U2.BJ20(VCCH) U2.BK19(VCC_HSSI_GXER1) U2.BL20(VCCH) U2.BP19(VCC_HSSI_GXER1) U2.BR20(VCC_HSSI_GXER1) U2.BT19(VCC_HSSI_GXER1) U2.BT43(VCCH_SDM) ; also on sheet 46 58 66
0p9V_VCCL_HPS: FB10.2 U2.AF23(VCCL_HPS) U2.AF25(VCCL_HPS) U2.AH23(VCCL_HPS) U2.AH25(VCCL_HPS) U2.AK23(VCCL_HPS) ; also on sheet 46 56 65
0p9V_VCCRT_GXER1: U2.AV15(VCCRT_GXER1) U2.AW14(VCCRT_GXER1) U2.AY15(VCCRT_GXER1) U2.BA14(VCCRT_GXER1) U2.BB15(VCCRT_GXER1) U2.BC14(VCCRT_GXER1) U2.BE14(VCCRT_GXER1) U2.BG14(VCCRT_GXER1) U2.BJ14(VCCRT_GXER1) U2.BK15(VCCRT_GXER1) U2.BL14(VCCRT_GXER1) U2.BM15(VCCRT_GXER1) U2.BN14(VCCRT_GXER1) U2.BP15(VCCRT_GXER1) ; also on sheet 58 65
0p9V_VCCRT_GXPL1: U2.AM49(VCCRT_GXPL1) U2.AN48(VCCRT_GXPL1) U2.AP49(VCCRT_GXPL1) U2.AR48(VCCRT_GXPL1) U2.AT49(VCCRT_GXPL1) U2.AV49(VCCRT_GXPL1) U2.AY49(VCCRT_GXPL1) U2.BB49(VCCRT_GXPL1) U2.BC48(VCCRT_GXPL1) U2.BD49(VCCRT_GXPL1) ; also on sheet 58 66
1p1V_VCCH_GXER1: U2.AY17(VCCH_GXER1) U2.BB17(VCCH_GXER1) U2.BK17(VCCH_GXER1) U2.BM17(VCCH_GXER1) U2.BP17(VCCH_GXER1) ; also on sheet 46 64 65
1p2V_DDR4_CH01: U2.AB25(VCCIO_PIO_3D) U2.AB27(VCCIO_PIO_3D) U2.AB29(VCCIO_PIO_3C) U2.AB31(VCCIO_PIO_3C) U2.AB33(VCCIO_PIO_3B) U2.AB35(VCCIO_PIO_3B) U2.AB37(VCCIO_PIO_3A) U2.AB39(VCCIO_PIO_3A) U2.AD25(VCCIO_PIO_3D) U2.AD27(VCCIO_PIO_3D) U2.AD29(VCCIO_PIO_3C) U2.AD31(VCCIO_PIO_3C) U2.AD33(VCCIO_PIO_3B) U2.AD35(VCCIO_PIO_3B) U2.AD37(VCCIO_PIO_3A) U2.AD39(VCCIO_PIO_3A) U2.BV43(VCCN_PIO_SDM) ; also on sheet 9 12 13 40 42 46 60 62 66
1p2V_DDR4_CH23: U2.BY25(VCCIO_PIO_2D) U2.BY27(VCCIO_PIO_2D) U2.BY29(VCCIO_PIO_2C) U2.BY31(VCCIO_PIO_2C) U2.BY33(VCCIO_PIO_2B) U2.BY35(VCCIO_PIO_2B) U2.BY37(VCCIO_PIO_2A) U2.BY39(VCCIO_PIO_2A) U2.CB25(VCCIO_PIO_2D) U2.CB27(VCCIO_PIO_2D) U2.CB29(VCCIO_PIO_2C) U2.CB31(VCCIO_PIO_2C) U2.CB33(VCCIO_PIO_2B) U2.CB35(VCCIO_PIO_2B) U2.CB37(VCCIO_PIO_2A) U2.CB39(VCCIO_PIO_2A) ; also on sheet 15 16 18 19 25 46 61 62 66
1p2V_VCCR: U2.AF37(VCCRCORE) U2.AH37(VCCRCORE) U2.AJ24(VCCRCORE) U2.AJ26(VCCRCORE) U2.AJ28(VCCRCORE) U2.BR24(VCCRCORE) U2.BR26(VCCRCORE) U2.BR28(VCCRCORE) U2.BT37(VCCRCORE) U2.BV37(VCCRCORE) ; also on sheet 59 65
1p8V: FB11.1 FB12.2 FB14.1 FB15.1 FB38.2 FB45.1 U2.AJ30(VCCPT) U2.AJ32(VCCPT) U2.AJ34(VCCPT) U2.AJ36(VCCPT) U2.BR30(VCCPT) U2.BR32(VCCPT) U2.BR34(VCCPT) U2.BR36(VCCPT) U2.CA48(VCCBAT) U2.CC48(VCCBAT) ; also on sheet 22 46 54 65
2p5V: C277.1 FB20.2 U2.AR18(VCCCLK_GXER1) ; also on sheet 9 12 15 18 21 63
CLK_DDR4_CH0_N: R248.1 ; also on sheet 11
CLK_DDR4_CH0_P: R246.1 ; also on sheet 11
CLK_DDR4_CH1_N: R250.1 ; also on sheet 14
CLK_DDR4_CH1_P: R249.1 ; also on sheet 14
CLK_DDR4_CH2_N: R252.1 ; also on sheet 17
CLK_DDR4_CH2_P: R251.1 ; also on sheet 17
CLK_DDR4_CH3_N: R254.1 ; also on sheet 20
CLK_DDR4_CH3_P: R253.1 ; also on sheet 20
CLK_SYS_100M_N: R256.1 ; also on sheet 19
CLK_SYS_100M_P: R255.1 ; also on sheet 19
CLK_SYS_BAK_50M_N: R258.1 ; also on sheet 13
CLK_SYS_BAK_50M_P: R257.1 ; also on sheet 13
EMMC_CLK: U16.M6(CLK) U16.N7(NC93) U16.P7(NC103) ; also on sheet 27
EMMC_CMD: R226.1 R235.1 ; also on sheet 27
EMMC_COMMAND: R226.2 U16.L1(NC73) U16.L2(NC74) U16.L3(NC75) U16.M5(CMD)
EMMC_DAT0: R220.2 U16.A3(DAT0)
EMMC_DAT1: R221.2 U16.A4(DAT1)
EMMC_DAT2: R222.2 U16.A5(DAT2)
EMMC_DAT3: R218.2 U16.A1(NC1) U16.B2(DAT3)
EMMC_DAT4: R223.2 U16.A2(NC2) U16.B3(DAT4)
EMMC_DAT5: R219.2 U16.B4(DAT5) U16.C3(NC20) U16.D1(NC30) U16.D2(NC31)
EMMC_DAT6: R224.2 U16.B5(DAT6) U16.C5(NC21)
EMMC_DAT7: R225.2 U16.A8(NC3) U16.B6(DAT7) U16.B7(NC11)
EMMC_DATA0: R220.1 R227.1 ; also on sheet 27
EMMC_DATA1: R221.1 R228.1 ; also on sheet 27
EMMC_DATA2: R222.1 R229.1 ; also on sheet 27
EMMC_DATA3: R218.1 R230.1 ; also on sheet 27
EMMC_DATA4: R223.1 R231.1 ; also on sheet 27
EMMC_DATA5: R219.1 R232.1 ; also on sheet 27
EMMC_DATA6: R224.1 R233.1 ; also on sheet 27
EMMC_DATA7: R225.1 R234.1 ; also on sheet 27
EMMC_RSTn: R236.1 U16.K5(RST_N) ; also on sheet 43
EN: R187.1 U14.20(EN)
FPGA_OSC_CLK_1: R259.1 ; also on sheet 26
FPGA_TEMP1n: U2.AH43(TEMPDIODE0CN) ; also on sheet 47
FPGA_TEMP1p: U2.AF43(TEMPDIODE0CP) ; also on sheet 47
FPGA_VCC: U2.AF27(VCCP) U2.AF29(VCCP) U2.AF31(VCCP) U2.AF33(VCCP) U2.AF35(VCCP) U2.AF41(VCC) U2.AH27(VCCP) U2.AH29(VCCP) U2.AH31(VCCP) U2.AH33(VCCP) U2.AH35(VCCP) U2.AH41(VCC) U2.AK21(VCC) U2.AK25(VCC) U2.AK27(VCC) U2.AK29(VCC) U2.AK31(VCC) U2.AK33(VCC) U2.AK35(VCC) U2.AK37(VCC) U2.AK39(VCC) U2.AK41(VCC) U2.AM21(VCC) U2.AM23(VCC) U2.AM25(VCC) U2.AM27(VCC) U2.AM29(VCC) U2.AM31(VCC) U2.AM33(VCC) U2.AM35(VCC) U2.AM37(VCC) U2.AM39(VCC) U2.AM41(VCC) U2.AP21(VCC) U2.AP23(VCC) U2.AP25(VCC) U2.AP37(VCC) U2.AP39(VCC) U2.AP41(VCC) U2.AT21(VCC) U2.AT23(VCC) U2.AT25(VCC) U2.AT37(VCC) U2.AT39(VCC) U2.AT41(VCC) U2.AV21(VCC) U2.AV23(VCC) U2.AV25(VCC) U2.AV37(VCC) U2.AV39(VCC) U2.AV41(VCC) U2.AY21(VCC) U2.AY23(VCC) U2.AY25(VCC) U2.AY37(VCC) U2.AY39(VCC) U2.AY41(VCC) U2.BB21(VCC) U2.BB23(VCC) U2.BB37(VCC) U2.BB39(VCC) U2.BB41(VCC) U2.BD21(VCC) U2.BD23(VCC) U2.BD25(VCC) U2.BD37(VCC) U2.BD39(VCC) U2.BD41(VCC) U2.BF21(VCC) U2.BF23(VCC) U2.BF25(VCC) U2.BF37(VCC) U2.BF39(VCC) U2.BF41(VCC) U2.BH21(VCC) U2.BH23(VCC) U2.BH25(VCC) U2.BH37(VCC) U2.BH39(VCC) U2.BH41(VCC) U2.BK21(VCC) U2.BK23(VCC) U2.BK25(VCC) U2.BK37(VCC) U2.BK39(VCC) U2.BK41(VCC) U2.BM21(VCC) U2.BM23(VCC) U2.BM25(VCC) U2.BM27(VCC) U2.BM29(VCC) U2.BM31(VCC) U2.BM33(VCC) U2.BM35(VCC) U2.BM37(VCC) U2.BM39(VCC) U2.BM41(VCC) U2.BP21(VCC) U2.BP23(VCC) U2.BP25(VCC) U2.BP27(VCC) U2.BP29(VCC) U2.BP31(VCC) U2.BP33(VCC) U2.BP35(VCC) U2.BP37(VCC) U2.BP39(VCC) U2.BP41(VCC) U2.BT21(VCC) U2.BT23(VCC) U2.BT27(VCCP) U2.BT29(VCCP) U2.BT31(VCCP) U2.BT33(VCCP) U2.BT35(VCCP) U2.BV21(VCC) U2.BV23(VCC) U2.BV27(VCCP) U2.BV29(VCCP) U2.BV31(VCCP) U2.BV33(VCCP) U2.BV35(VCCP) ; also on sheet 46 52 53 65 66
HPS_JTAG_TCK: R198.1 ; also on sheet 44
HPS_JTAG_TDI: R200.1 ; also on sheet 44
HPS_JTAG_TDO: R197.1 ; also on sheet 44
HPS_JTAG_TMS: R199.1 ; also on sheet 44
HPS_OSC_CLK: R834.1 ; also on sheet 27
IO_1p8V: C258.2 C270.1 C271.1 C272.1 C273.1 FB19.1 FB22.2 R181.1 R182.1 R183.1 R184.1 R185.1 R186.1 R190.2 R205.2 R207.2 R210.1 R212.2 R213.2 R214.1 R215.1 R216.1 R227.2 R228.2 R229.2 R230.2 R231.2 R232.2 R233.2 R234.2 R235.2 R236.2 U2.AD21(VCCIO_HPS) U2.AF21(VCCIO_HPS) U2.AH21(VCCIO_HPS) U2.BY41(VCCIO_SDM) U2.CB41(VCCIO_SDM) U14.2(Vref_A) U16.C6(VCCQ1) U16.M4(VCCQ2) U16.N4(VCCQ3) U16.P3(VCCQ4) U16.P5(VCCQ5) ; also on sheet 26 28 29 39 40 46 57 65
IO_3p3V: C264.1 C267.1 C268.1 C269.1 C304.1 FB21.1 R243.2 R244.2 R245.2 R247.2 U15.A2(Vin) U16.E6(VCC1) U16.F5(VCC2) U16.J10(VCC3) U16.K9(VCC4) ; also on sheet 12 23 24 25 28 39 40 41 42 63
LOGIC0A: J12.30(Logic0A) R208.2
LOGIC0B: J12.32(Logic0B) R209.2
LOGIC1: J12.34(LOGIC1) R210.2
MAIN_I2C_SCL: U17.16(SCLK) ; also on sheet 39 40 44 46 47 54
MAIN_I2C_SDA: U17.18(SDA_SDIO) ; also on sheet 39 40 44 46 47 54
MICTOR_JTAG_TCK: J12.15(TCK) R198.2 R217.2 ; also on sheet 27
MICTOR_JTAG_TDI: J12.19(TDI) R200.2 R214.2 ; also on sheet 27
MICTOR_JTAG_TDO: J12.11(TDO/SWO) R197.2 R215.2 ; also on sheet 27
MICTOR_JTAG_TMS: J12.17(TMS) R199.2 R216.2 ; also on sheet 27
MICTOR_JTAG_TRSTn: J12.21(nTRST) R213.1
MICTOR_PWR1: J12.12(VTREF) R205.1
MICTOR_SRSTn: J12.9(nSRST) R212.1 ; also on sheet 43
REFCLK_156M_QSFPDD_N: C316.2 ; also on sheet 21
REFCLK_156M_QSFPDD_P: C315.2 ; also on sheet 21
REFCLK_322M_QSFPDD_N: C318.2 ; also on sheet 21
REFCLK_322M_QSFPDD_P: C317.2 ; also on sheet 21
SD_3.3V: C259.2 C261.1 C262.2 C263.2 J11.4(VDD) R180.2 R188.1 U15.A1(Vout)
SD_CLK: R181.2 U14.10(A8) ; also on sheet 27
SD_CLK_3.3V: D6.1(K1) J11.5(CLK) R195.1 U14.11(B8)
SD_CMD: R182.2 U14.9(A7) ; also on sheet 27
SD_CMD_3.3V: D6.2(K2) J11.3(CMD) R194.1 U14.12(B7)
SD_DATA0: R183.2 U14.5(A3) ; also on sheet 27
SD_DATA0_3.3V: D5.1(K1) J11.7(DAT0) R189.1 U14.16(B3)
SD_DATA1: R184.2 U14.6(A4) ; also on sheet 27
SD_DATA1_3.3V: D5.2(K2) J11.8(DAT1) R191.1 U14.15(B4)
SD_DATA2: R185.2 U14.7(A5) ; also on sheet 27
SD_DATA2_3.3V: D4.1(K1) J11.1(DAT2) R192.1 U14.14(B5)
SD_DATA3: R186.2 U14.8(A6) ; also on sheet 27
SD_DATA3_3.3V: D4.2(K2) J11.2(CD/DAT3) R193.1 R196.2 U14.13(B6)
SD_RSTn: R190.1 U15.B2(ON) ; also on sheet 43
SI5341_1p8V_VDDO: C307.1 C308.1 C309.1 C310.1 C311.1 C312.1 C313.1 C314.1 FB22.1 U17.26(VDDO1) U17.29(VDDO2) U17.33(VDDO3) U17.36(VDDO4) U17.43(VDDO6) U17.49(VDDO7) U17.52(VDDO8) U17.57(VDDO9)
SI5341_2p5V_VDDO: C302.1 C303.1 FB20.1 U17.22(VDDO0) U17.40(VDDO5)
SI5341_A0: R241.1 U17.19(A0_CSB)
SI5341_A1: R242.1 U17.17(A1_SDO)
SI5341_ENn: U17.11(OEB) ; also on sheet 39 44
SI5341_FDEC: U17.25(FDEC) ; also on sheet 43
SI5341_FINC: U17.48(FINC) ; also on sheet 43
SI5341_I2C_SEL: R243.1 U17.39(I2C_SEL)
SI5341_IN_SEL0: R245.1 U17.3(IN_SEL0)
SI5341_IN_SEL1: R244.1 U17.4(IN_SEL1)
SI5341_OUT0n: C316.1 U17.23(OUT0B)
SI5341_OUT0p: C315.1 U17.24(OUT0)
SI5341_OUT1n: R250.2 U17.27(OUT1B)
SI5341_OUT1p: R249.2 U17.28(OUT1)
SI5341_OUT2n: R254.2 U17.30(OUT2B)
SI5341_OUT2p: R253.2 U17.31(OUT2)
SI5341_OUT3n: R248.2 U17.34(OUT3B)
SI5341_OUT3p: R246.2 U17.35(OUT3)
SI5341_OUT4n: R252.2 U17.37(OUT4B)
SI5341_OUT4p: R251.2 U17.38(OUT4)
SI5341_OUT5n: C318.1 U17.41(OUT5B)
SI5341_OUT5p: C317.1 U17.42(OUT5)
SI5341_OUT6n: R256.2 U17.44(OUT6B)
SI5341_OUT6p: R255.2 U17.45(OUT6)
SI5341_OUT7n: R258.2 U17.50(OUT7B)
SI5341_OUT7p: R257.2 U17.51(OUT7)
SI5341_OUT8p: R259.2 U17.54(OUT8)
SI5341_OUT9p: R834.2 U17.59(OUT9)
SI5341_RSTn: R247.1 U17.6(RSTB) ; also on sheet 44
SI5341_VDD: C298.1 C299.1 C300.1 C301.1 FB19.2 U17.32(VDD) U17.46(VDD) U17.60(VDD)
SI5341_VDDA: C305.1 C306.1 FB21.2 U17.13(VDDA)
SI5341_X1: U17.7(X1) Y2.2
SI5341_X2: U17.10(X2) Y2.4
SI5341_XA: U17.8(XA) Y2.3
SI5341_XB: U17.9(XB) Y2.1
TRACECTL: J12.36(TRACECTL) R211.2
VREF_B: C260.2 R180.1 R187.2 U14.19(Vref_B)
N35982389: R188.2 R189.2 R191.2 R192.2 R193.2 R194.2 R195.2
N35984757: J12.6(TRACECLK) R201.2
N35984782: J12.8(TRIGOUT) R203.2
N35984815: J12.10(NC) R204.2
N35984874: J12.13(RTCK) R206.1
N35984876: J12.14(Vsupply) R207.1
N36194618: C1219.1 C1220.1 FB45.2 U2.BY43(VCCADC) U2.CB43(VCCADC)
N42720682: J12.7(TRIGIN) R202.1

Not connected (* = marked no-connect by the designer): J12 1(NC1)* 2(NC3)* 3(NC2)* 4(NC4)*; U2 AA10(NC83)* AA12(NC82)* AA14(NC81)* AA16(NC80)* AA18(NC79)* AA20(NC78)* AA42(NC77)* AA44(NC76)* AA46(NC75)* AA48(NC74)* AA52(NC73)* AA56(NC72)* AA62(NC71)* AB11(NC70)* AB13(NC69)* AB15(NC68)* AB17(NC67)* AB19(NC66)* AB43(NC65)* AB45(NC64)* AB47(NC63)* AB55(NC62)* AB61(NC61)* AC14(NC60)* AC16(NC59)* AC18(NC58)* AC42(NC57)* AC44(NC56)* AC46(NC55)* AC56(NC54)* AC62(NC53)* AD15(NC52)* AD17(NC51)* AD19(DNU11)* AD43(NC50)* AD45(DNU9)* AE44(DNU13)* AF19(DNU15)* AJ46(DNU20)* BK49(DNU22)* BL44(DNU25)* BL46(DNU32)* BL48(DNU24)* BL50(DNU49)* BM45(DNU43)* BM47(DNU41)* BM49(DNU23)* BN44(DNU37)* BN46(DNU34)* BN50(DNU21)* BP47(DNU36)* BR50(DNU33)* BT45(DNU44)* BT47(DNU48)* BT49(DNU27)* BT51(DNU31)* BT53(DNU40)* BT59(NC49)* BU14(NC48)* BU16(NC47)* BU44(DNU26)* BU46(DNU45)* BU48(DNU46)* BU50(DNU30)* BU52(DNU38)* BU60(NC46)* BV13(NC45)* BV15(NC44)* BV17(NC43)* BV19(NC42)* BV45(DNU42)* BV47(DNU47)* BV49(DNU28)* BV51(DNU29)* BV53(DNU35)* BV55(DNU39)* BW18(DNU10)* BY15(NC41)* BY17(NC40)* BY19(DNU14)* BY21(NC39)* BY57(NC38)* BY61(DNU12)* CA14(NC37)* CA16(NC36)* CA18(NC35)* CA50(NC34)* CA56(NC33)* CB1(NC32)* CB7(NC25)* CB13(NC31)* CB15(NC30)* CB17(NC29)* CB19(NC28)* CB21(NC27)* CB51(NC26)* CB61(DNU8)* CC2(NC21)* CC8(NC17)* CC14(NC24)* CC16(NC23)* CC18(NC22)* CC20(NC20)* CC22(NC19)* CC50(NC18)* CF1(NC16)* CH1(NC15)* CK1(NC14)* CK61(NC13)* CM1(NC12)* CM61(NC11)* G62(NC10)* J62(NC9)* L62(NC8)* M61(NC7)* N62(NC6)* P61(NC5)* T61(NC4)* U62(NC3)* V61(NC2)* W62(NC1)*; U14 3(A1)* 4(A2)* 17(B2)* 18(B1)*; U16 A7(RFU1)* A9(NC4)* A10(NC5)* A11(NC6)* A12(NC7)* A13(NC8)* A14(NC9)* B1(NC10)* B8(NC12)* B9(NC13)* B10(NC14)* B11(NC15)* B12(NC16)* B13(NC17)* B14(NC18)* C7(NC22)* C8(NC23)* C9(NC24)* C10(NC25)* C11(NC26)* C12(NC27)* C13(NC28)* C14(NC29)* D3(NC32)* D12(NC34)* D13(NC35)* D14(NC36)* E1(NC37)* E2(NC38)* E3(NC39)* E5(RFU2)* E8(RFU3)* E9(RFU4)* E10(RFU5)* E12(NC40)* E13(NC41)* E14(NC42)* F1(NC43)* F2(NC44)* F3(NC45)* F10(RFU6)* F12(NC46)* F13(NC47)* F14(NC48)* G1(NC49)* G2(NC50)* G3(NC51)* G10(RFU7)* G12(NC52)* G13(NC53)* G14(NC54)* H1(NC55)* H2(NC56)* H3(NC57)* H5(DS)* H12(NC58)* H13(NC59)* H14(NC60)* J1(NC61)* J2(NC62)* J3(NC63)* J12(NC64)* J13(NC65)* J14(NC66)* K1(NC67)* K2(NC68)* K3(NC69)* K6(RFU8)* K7(RFU9)* K10(RFU10)* K12(NC70)* K13(NC71)* K14(NC72)* L12(NC76)* L13(NC77)* L14(NC78)* M1(NC79)* M2(NC80)* M3(NC81)* M7(NC82)* M8(NC83)* M9(NC84)* M10(NC85)* M11(NC86)* M12(NC87)* M13(NC88)* M14(NC89)* N3(NC91)* N6(NC92)* N8(NC94)* N9(NC95)* N10(NC96)* N11(NC97)* N12(NC98)* N13(NC99)* N14(NC100)* P1(NC101)* P2(NC102)* P8(NC104)* P9(NC105)* P10(RFU11)* P11(NC106)* P12(NC107)* P13(NC108)* P14(NC109)*; U17 1(IN1)* 2(IN1_N)* 5(SYNCB)* 12(INTRB)* 14(IN2)* 15(IN2_N)* 20(RSVD1)* 21(RSVD2)* 47(LOLB)* 53(OUT8B)* 55(RSVD3)* 56(RSVD4)* 58(OUT9B)* 61(FBIN)* 62(FBIN_N)* 63(IN0)* 64(IN0_N)*

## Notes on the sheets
sheet 30
- MicroSD Card
- Micro SD Card
- The B-side pullup resistors should
  be sized according to signal frequency and current limits
- ON Vih Threhold: 0.85V
- IEC61000-4-2 (ESD): ± 20 kV (air / contact)
- IEC61000-4-4 (EFT): ±50 A (5/50 ns)
- IEC61000-4-5 (surge): ±3 A (8/20 µs)
sheet 31
- eMMC
- DS is used in HS400 mode
sheet 32
- Bank NC/DNU
- NOTE: This pins are
  for internal use only
sheet 33
- FPGA Power 1
sheet 34
- FPGA Power 2
sheet 35
- FPGA GND 1
sheet 36
- FPGA GND 2
sheet 37
- FPGA GND 3
sheet 38
- Clock 1
- set IO_VDD_SEL = 1,
  select VDDIO = VDDA
- 7-bit I2C Address 74h
- Default LVDS 156.25 MHz
- Default LVDS 33.333 MHz
- Default LVDS 33.333 MHz
- Default LVDS 33.333 MHz
- Default LVDS 33.333 MHz
- Default LVDS 322.265625 MHz
- Default LVDS 100 MHz
- Default LVDS 50 MHz
- Default LVCMOS 125 MHz
- Default LVCMOS 25 MHz
